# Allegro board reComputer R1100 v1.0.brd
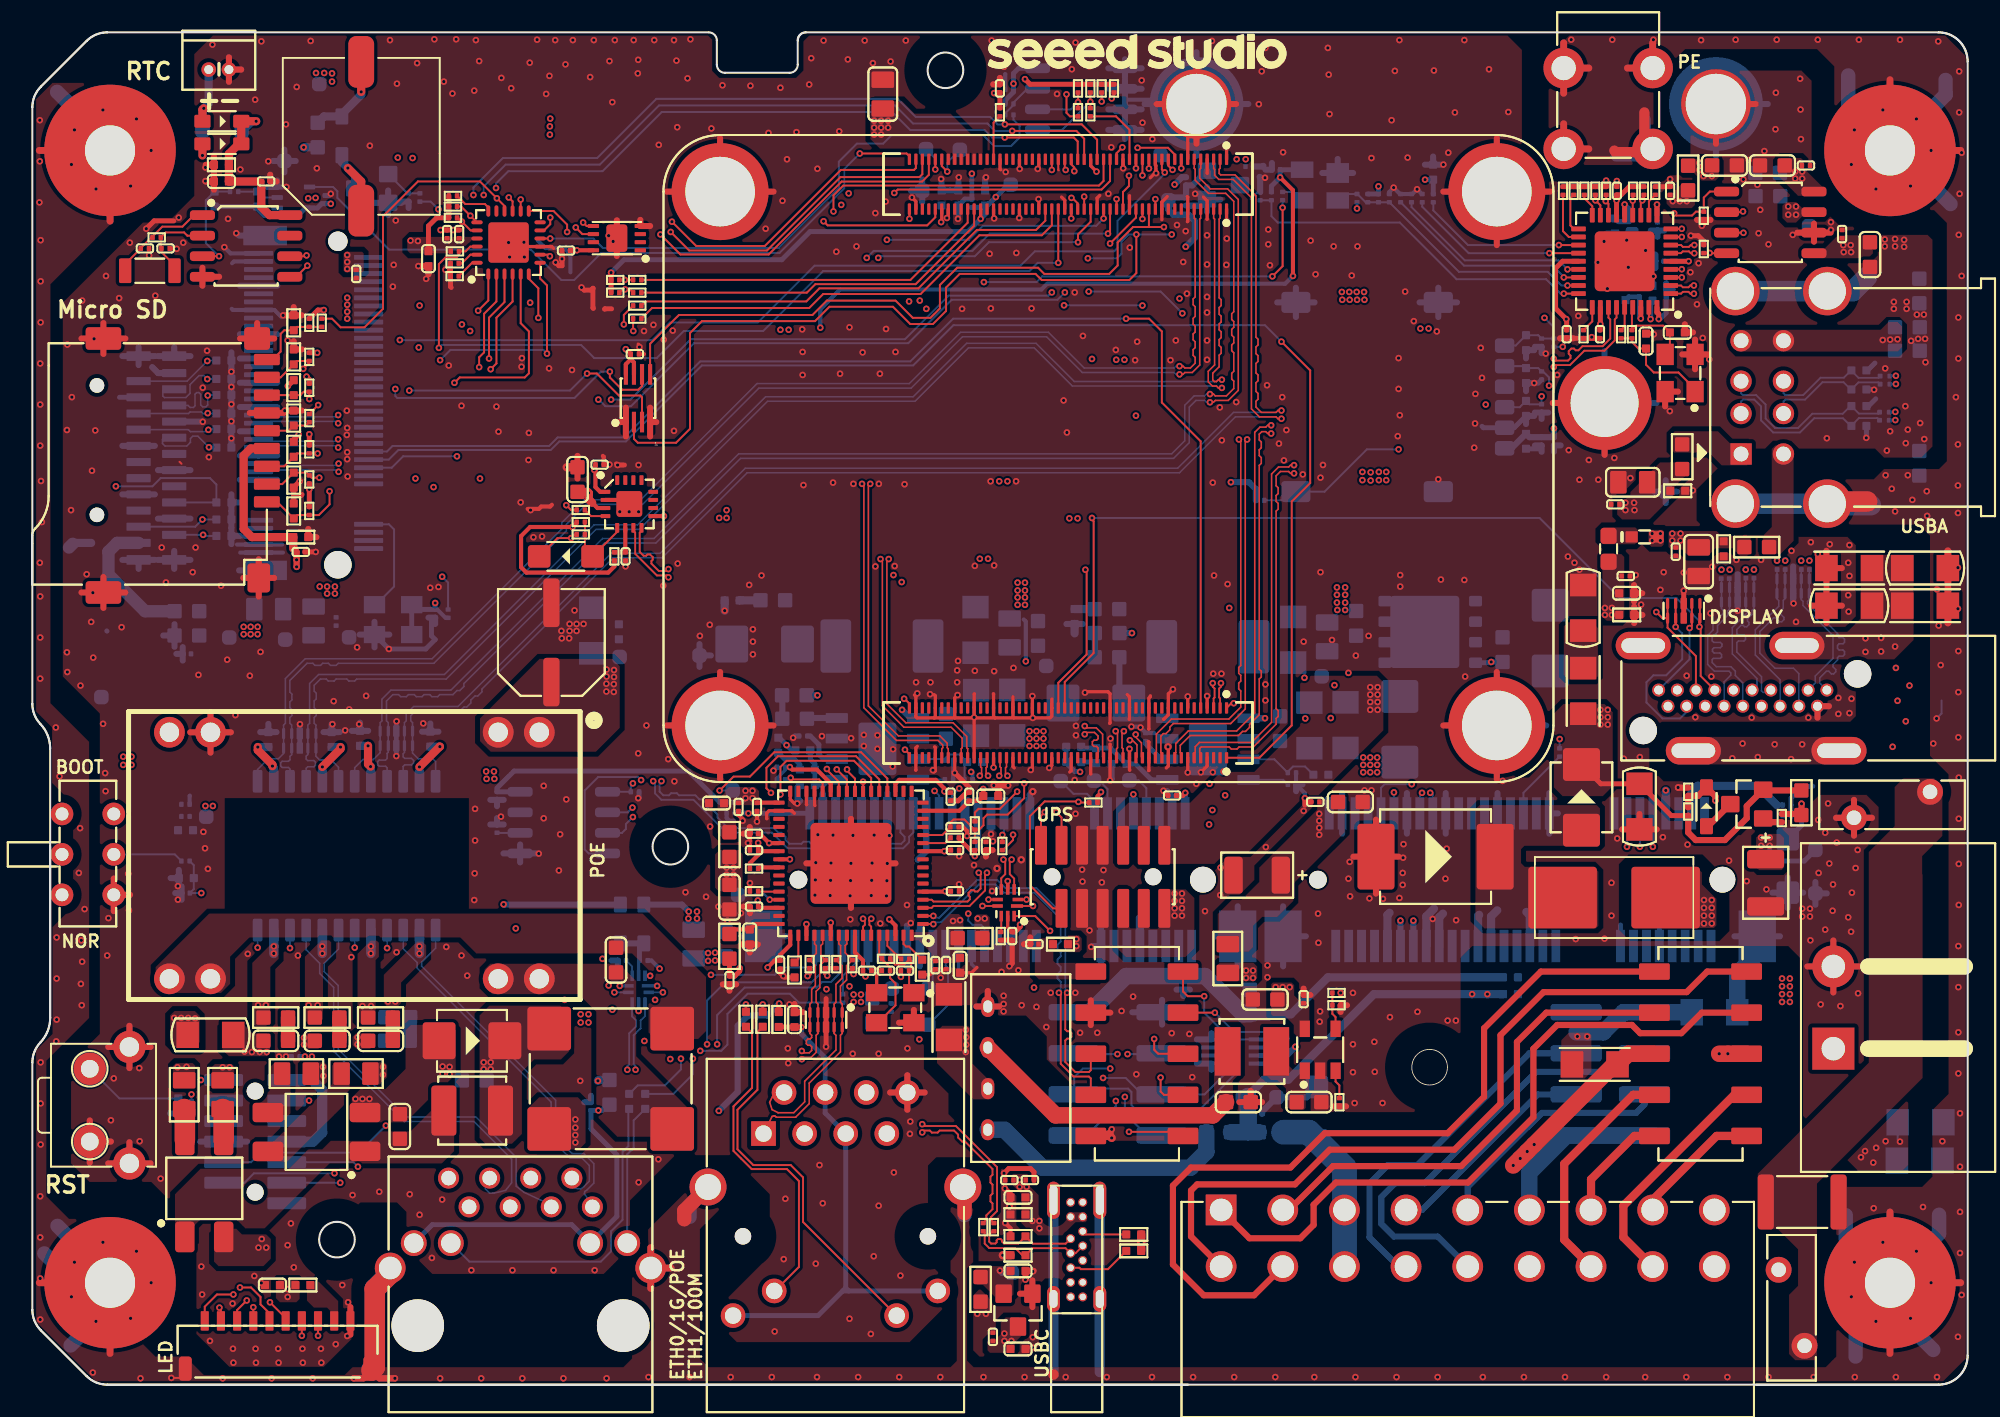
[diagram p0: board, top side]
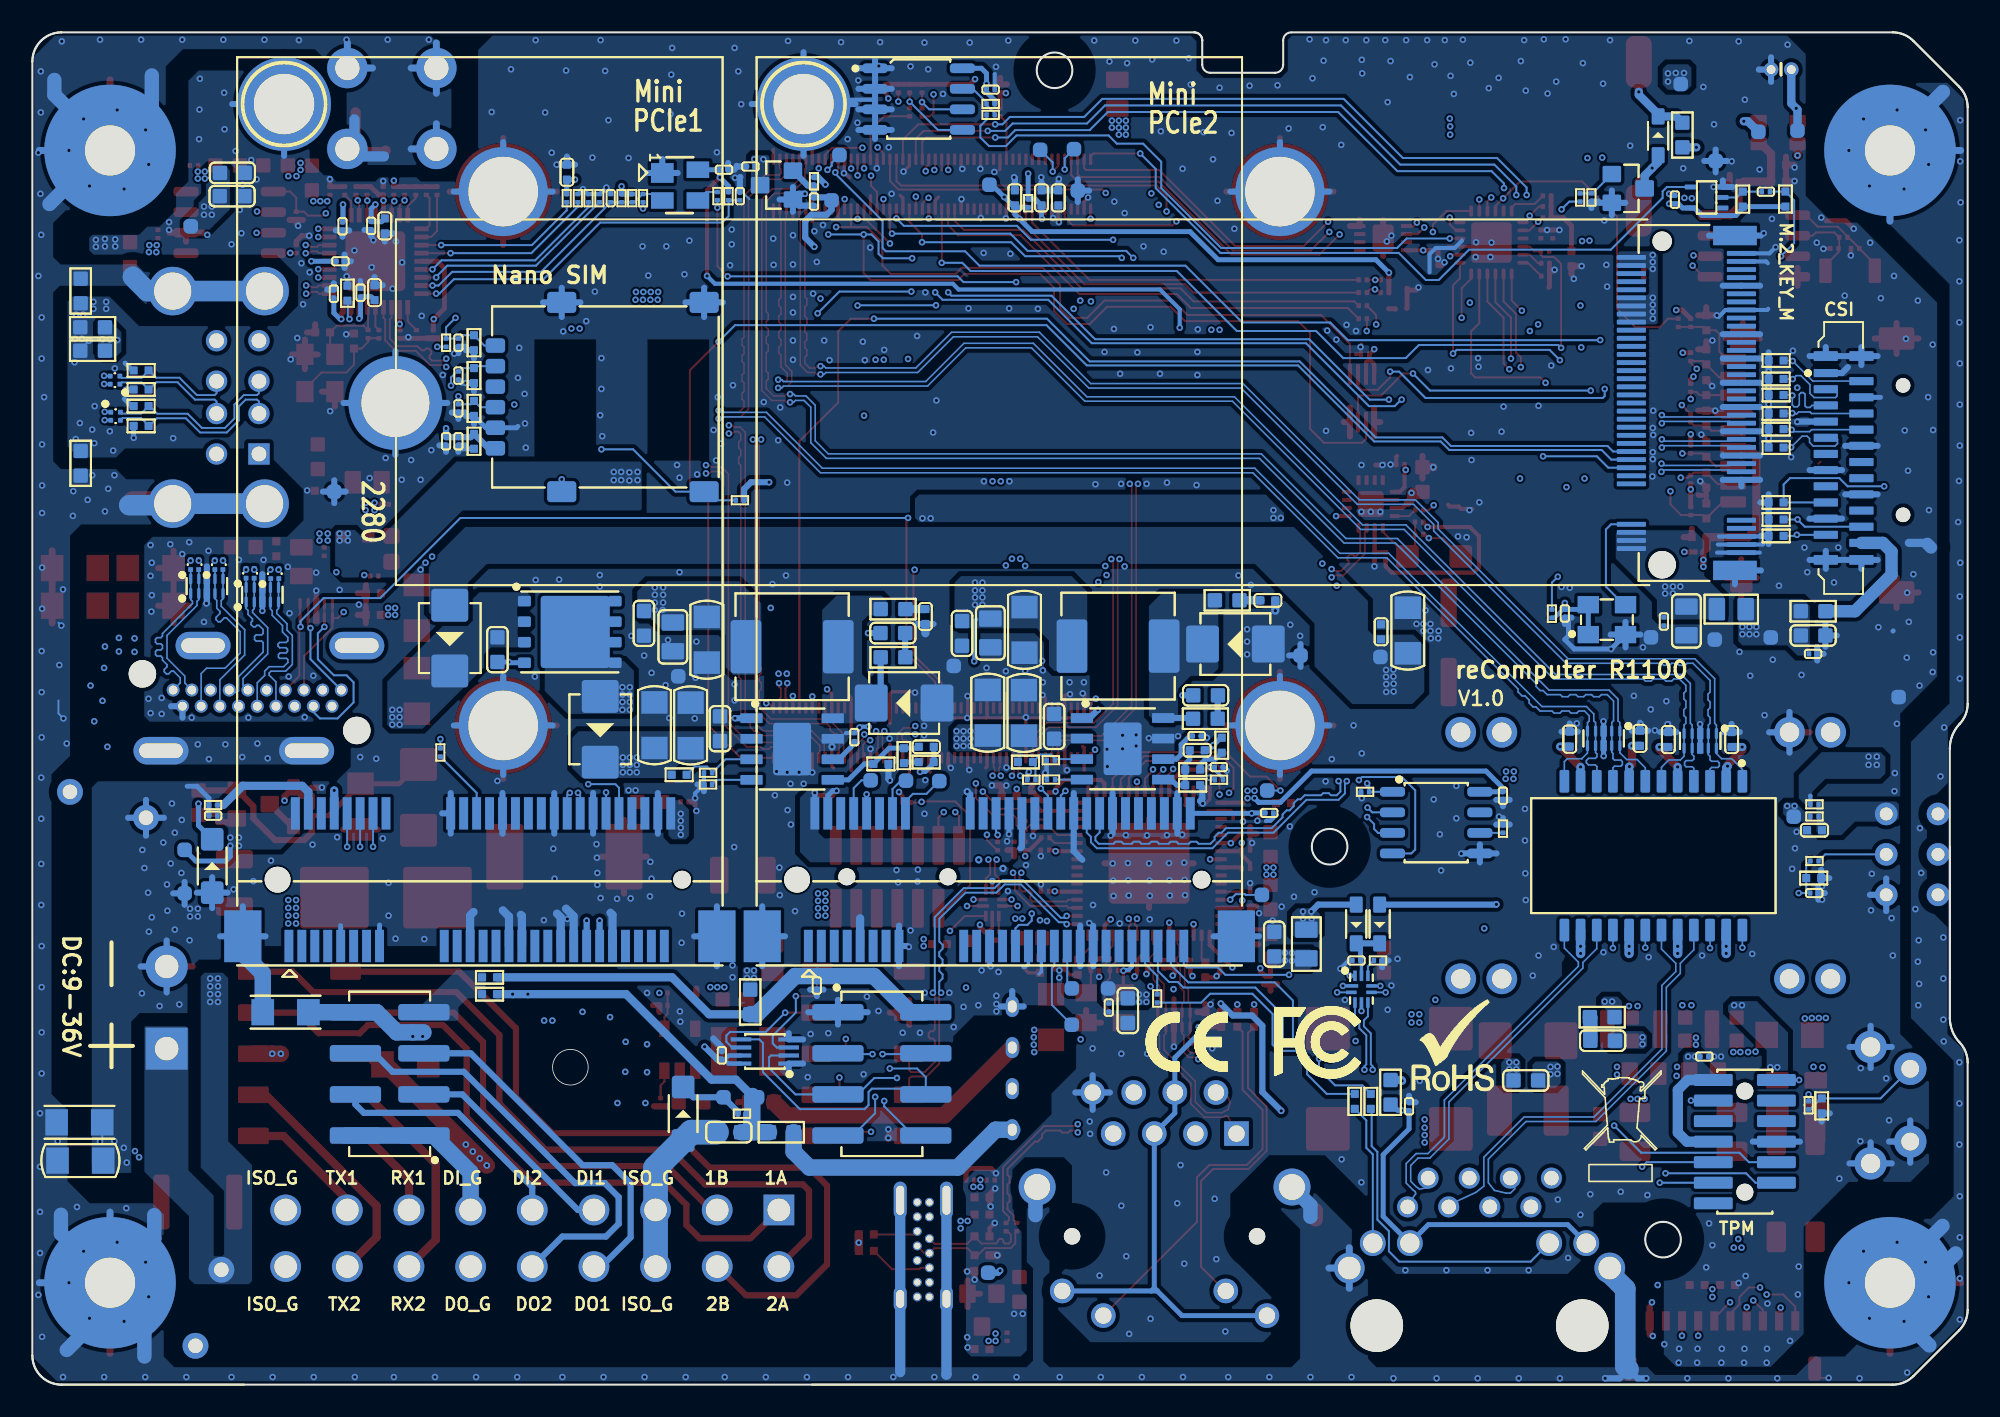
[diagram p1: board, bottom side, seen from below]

Outline 119.6 x 83.6 mm; copper layers: TOP, LYR2_GND, LYR3, LYR4_GND, LYR5_PWR, LYR6, LYR7_GND, BOTTOM. Coordinates in mm from the lower left corner of the outline.
Outline path: circle c18.82,8.97 r1.1 ; circle c18.82,8.97 r1.1 ; circle c39.43,33.26 r1.1 ; circle c39.43,33.26 r1.1 ; circle c56.43,81.25 r1.1 ; circle c56.43,81.25 r1.1 ; circle c86.35,19.62 r1.1 ; 0,78.97 0,42.09 ; 0,78.97 arc(0.14,79.66) 0.53,80.24 ; 0,78.97 arc(0.14,79.66) 0.53,80.24 ; 0,42.09 arc(0.13,41.42) 0.5,40.85 ; 0,42.09 arc(0.13,41.42) 0.5,40.85 ; 0.53,80.24 3.36,83.07 ; 0.53,80.24 3.36,83.07 ; 0,19.91 0,4.63 ; 0,19.91 arc(0.13,20.58) 0.5,21.15 ; 0,19.91 arc(0.13,20.58) 0.5,21.15 ; 0,4.63 arc(0.14,3.94) 0.53,3.36 ; 0,4.63 arc(0.14,3.94) 0.53,3.36 ; 0.5,21.15 arc(0.94,21.85) 1.1,22.67 ; 0.5,21.15 arc(0.94,21.85) 1.1,22.67 ; 0.5,40.85 arc(0.94,40.15) 1.1,39.33 ; 0.5,40.85 arc(0.94,40.15) 1.1,39.33 ; 1.1,39.33 1.1,22.67 ; 3.36,83.07 arc(3.94,83.46) 4.63,83.6 ; 3.36,83.07 arc(3.94,83.46) 4.63,83.6 ; 0.53,3.36 3.36,0.53 ; 0.53,3.36 3.36,0.53 ; 3.36,0.53 arc(3.94,0.14) 4.63,0 ; 3.36,0.53 arc(3.94,0.14) 4.63,0 ; 1.1,22.67 1.1,33.26 ; 4.63,83.6 41.8,83.6 arc(42.15,83.45) 42.3,83.1 42.3,81.6 arc(42.45,81.25) 42.8,81.1 46.8,81.1 arc(47.15,81.25) 47.3,81.6 47.3,83.1 ; 4.63,0 71.42,0 ; 4.63,0 117.8,0 ; 117.8,0 106.52,0 ; 117.8,0 arc(119.07,0.53) 119.6,1.8 ; 117.8,0 arc(119.07,0.53) 119.6,1.8 ; 47.3,83.1 arc(47.45,83.45) 47.8,83.6 ; 47.3,83.1 arc(47.45,83.45) 47.8,83.6 ; 47.8,83.6 117.8,83.6 ; 117.8,83.6 arc(119.07,83.07) 119.6,81.8 ; 117.8,83.6 arc(119.07,83.07) 119.6,81.8 ; 119.6,81.8 119.6,1.8

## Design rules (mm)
constraint set DEFAULT: min track width 0.121
net group CAM0_C: nets CAM0_C_N CAM0_C_P
net group CAM0_D0: nets CAM0_D0_N CAM0_D0_P
net group CAM0_D1: nets CAM0_D1_N CAM0_D1_P
net group DP_HDMI0_CLK_N1: nets HDMI0_CLK_N HDMI0_CLK_P
net group DP_HDMI0_TX0: nets HDMI0_TX0_N HDMI0_TX0_P
net group DP_HDMI0_TX1_N1: nets HDMI0_TX1_N HDMI0_TX1_P
net group DP_HDMI0_TX2_N1: nets HDMI0_TX2_N HDMI0_TX2_P
net group ETHERNET0: nets ETHERNET_PAIR0_N ETHERNET_PAIR0_P
net group ETHERNET1: nets ETHERNET_PAIR1_N ETHERNET_PAIR1_P
net group ETHERNET2: nets ETHERNET_PAIR2_N ETHERNET_PAIR2_P
net group ETHERNET3: nets ETHERNET_PAIR3_N ETHERNET_PAIR3_P
net group ETHERNET_RX_P: nets ETHERNET_RX_N ETHERNET_RX_P
net group ETHERNET_TX_P: nets ETHERNET_TX_N ETHERNET_TX_P
net group HDMI0_CLK_N1: nets HDMI0_CLK_N1 HDMI0_CLK_P1
net group HDMI0_TX0_N1: nets HDMI0_TX0_N1 HDMI0_TX0_P1
net group HDMI0_TX1_N1: nets HDMI0_TX1_N1 HDMI0_TX1_P1
net group HDMI0_TX2_N1: nets HDMI0_TX2_N1 HDMI0_TX2_P1
net group N21891930: nets N21891930 N21894342
net group N23452007: nets N23452007 N23452027
net group PCIE_CLK: nets PCIE_CLK_N PCIE_CLK_P
net group PCIE_RX: nets PCIE_RX_N PCIE_RX_P
net group PCIE_TX: nets PCIE_TX_N PCIE_TX_P
net group RJ_12: nets N22026897 N22026906
net group RJ_36: nets N22026915 N22078660
net group RJ_45: nets N22078676 N22078685
net group RJ_78: nets N22026957 N22026966
net group UART_3V3: nets UART_3V3 V3
net group USB_0: nets USB_0M USB_0P
net group USB_1P: nets USB_1M USB_1P
net group USB_D: nets USB_DM USB_DP
net group USB_HUB1_DM2: nets USB_HUB1_DM2 USB_HUB1_DP2
net group USB_HUB1_DM3: nets USB_HUB1_DM3 USB_HUB1_DP3
net group USB_HUB2_D1: nets USB_HUB2_DM1 USB_HUB2_DP1
net group USB_HUB2_D2: nets USB_HUB2_DM2 USB_HUB2_DP2
net group USB_HUB2_D3: nets USB_HUB2_DM3 USB_HUB2_DP3
net group USB_HUB2_D4: nets USB_HUB2_DM4 USB_HUB2_DP4
net group USB_HUB2_DP1_01: nets N23711005 N23711301
net group USB_HUB2_DP2_01: nets N23452966 N23452985
net group USB_TO_UART: nets USB_TO_UART_DM USB_TO_UART_DP
net group USBC: nets USB_C_DM USB_C_DP
net group USBC_DM: nets USBC_DM USBC_DP
net group VDD33_HUB1: nets N23370571 N23401903
net group +1.8V_OUT: nets USIM_1V8
net group +3.3V_OUT: nets +3.3V_OUT CM4_GPIO_VREF SD_VDD_OVERRIDE

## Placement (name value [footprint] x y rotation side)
B1  HPD-9603S-3  [BUZZER2P_8D4_9_6X9_6X5_5MM]  20.32 77.18 0 top
C1  100nF  [C0603]  90.86 45.44 270 bottom
C2  10uF  [C1206]  99.32 35.74 270 top
C3  4.7uF  [C1206]  95.84 48.03 90 top
C4  100nF  [C0201]  71.12 24.67 270 bottom
C5  100nF  [C0603]  66.42 46.46 180 bottom
C6  4.7uF  [C0402]  59.23 36.39 0 top
C7  10uF  [C1206]  78.92 40.76 90 bottom
C8  10uF  [C1206]  81.16 40.77 90 bottom
C9  100nF  [C0603]  77.11 40.55 90 bottom
C10  100nF  [C0603]  81.81 47.07 270 bottom
C11  22uF  [C0805]  80.02 46.23 270 bottom
C12  100uF  [C1206]  77.92 46.05 270 bottom
C13  100uF  [C1206]  58.29 46.66 270 bottom
C14  100nF  [C0201]  44.59 34.06 180 top
C15  10nF  [C0201]  68.8 40.03 90 bottom
C16  150pF  [C0402]  64.41 47.49 270 bottom
C17  150pF  [C0402]  64.35 39.43 0 bottom
C18  100nF  [C0603]  47.09 42.62 180 bottom
C19  100nF  [C0201]  57.9 36.35 90 top
C20  10uF  [C1206]  60.56 41.54 90 bottom
C21  10uF  [C1206]  58.32 41.53 90 bottom
C22  100nF  [C0603]  56.46 40.69 90 bottom
C23  100nF  [C0603]  62.15 46.44 270 bottom
C24  22uF  [C0805]  60.39 46.47 270 bottom
C28  10nF  [C0201]  47.64 40.1 180 bottom
C29  150pF  [C0402]  43.25 48.48 180 bottom
C30  150pF  [C0402]  47.61 39.22 0 bottom
C31  22uF  [C0805]  52.56 79.78 90 top
C32  100nF  [C0201]  59.79 80.13 90 top
C33  10uF  [C0402]  57.23 73.37 270 bottom
C34  10uF  [C0402]  56.2 73.37 270 bottom
C35  1uF  [C0402]  58.88 73.37 270 bottom
C36  1uF  [C0402]  9.47 34.28 0 bottom
C37  100nF  [C0201]  9.48 30.39 180 bottom
C38  100nF  [C0201]  60.56 27.73 270 top
C40  100nF  [C0201]  46.28 38.18 180 bottom
C41  100nF  [C0201]  44.78 35.71 270 top
C42  10uF  [C0603]  43.08 30.14 270 top
C43  100nF  [C0201]  43.64 35.71 270 top
C44  4.7uF  [C0402]  42.28 35.95 180 top
C45  100nF  [C0201]  44.6 29.56 180 top
C46  100nF  [C0201]  44.6 33.04 180 top
C47  100nF  [C0201]  56.75 36.35 270 top
C48  4.7uF  [C0402]  57.33 25.92 270 top
C49  100nF  [C0201]  55.8 25.94 270 top
C50  100nF  [C0201]  51.59 25.59 0 top
C51  100nF  [C0201]  57.02 33.04 0 top
C52  100nF  [C0201]  56.47 25.94 270 top
C53  100nF  [C0201]  46.21 25.97 270 top
C54  100nF  [C0201]  57.02 30.5 0 top
C55  100nF  [C0201]  56.99 34.48 0 top
C56  12pF  [C0201]  53.93 25.59 180 top
C57  12pF  [C0201]  52.75 25.59 180 top
C58  10uF  [C0603]  104.57 75.37 0 top
C59  100nF  [C0201]  101.21 73.81 90 top
C60  100nF  [C0201]  75.88 73.47 90 bottom
C61  100nF  [C0201]  83.86 73.35 90 bottom
C62  100nF  [C0201]  100.43 71.61 270 bottom
C63  100nF  [C0201]  96.88 64.94 270 top
C64  100nF  [C0201]  94.82 64.94 270 top
C65  100nF  [C0201]  100.56 69.45 180 bottom
C66  100nF  [C0201]  100.97 67.44 90 bottom
C67  100nF  [C0201]  97.92 73.81 90 top
C68  100nF  [C0201]  76.86 75.11 180 bottom
C69  1uF  [C0402]  98.45 67.51 270 bottom
C70  10nF  [C0201]  99.32 67.5 270 bottom
C71  1uF  [C0402]  97.82 71.64 90 bottom
C72  10nF  [C0201]  98.66 71.64 90 bottom
C73  1uF  [C0402]  86.57 74.96 90 bottom
C74  33pF  [C0402]  99.73 64.52 90 top
C75  33pF  [C0402]  101.66 65.05 0 top
C76  10uF  [C0805]  98.9 55.79 0 top
C77  10uF  [C0805]  102.98 50.88 270 top
C78  100nF  [C0201]  97.83 54.42 0 top
C79  100nF  [C0201]  101.56 51.5 270 top
C80  10uF  [C0603]  107.26 73.47 180 bottom
C81  10uF  [C0603]  107.24 74.91 180 bottom
C82  10uF  [C0603]  107.53 75.37 180 top
C83  100nF  [C0201]  109.61 75.37 0 top
C84  10uF  [C0603]  113.56 69.86 270 top
C85  100nF  [C0201]  111.84 71.13 90 top
C86  100nF  [C0201]  98.47 49.99 0 top
C87  1uF  [C0402]  98.52 48.92 0 top
C88  22nF  [C0402]  47.1 22.57 90 top
C89  1uF  [C0402]  24.48 69.61 270 top
C90  100nF  [C0201]  26.38 71.13 90 top
C91  100nF  [C0201]  25.63 71.13 90 top
C92  1uF  [C0402]  60.91 11.58 180 top
C93  100nF  [C0201]  61.65 12.65 0 top
C94  100nF  [C0201]  60.38 12.65 180 top
C95  1uF  [C0402]  60.91 2.21 0 top
C96  100nF  [C0201]  59.36 2.96 90 top
C97  1uF  [C0402]  60.91 7.03 0 top
C98  100nF  [C0201]  37.77 26.22 0 bottom
C99  10uF  [C0603]  33.69 55.95 270 top
C100  100nF  [C0201]  35.06 56.87 180 top
C101  100nF  [C0201]  36.66 51.2 90 top
C102  18pF  [C0201]  8.23 70.24 180 top
C103  18pF  [C0201]  6.95 70.24 0 top
C104  1uF  [C0402]  11.68 74.38 180 top
C105  100nF  [C0201]  14.44 74.39 0 top
C106  100nF  [C0201]  16.27 20.28 180 bottom
C107  100nF  [C0201]  60.38 80.06 180 bottom
C108  100nF  [C0201]  18.09 73.26 90 bottom
C109  100nF  [C0201]  12.47 73.75 0 bottom
C110  100nF  [C0201]  32.98 70.11 0 top
C111  100nF  [C0201]  108.43 35.17 0 bottom
C112  100nF  [C0201]  70.44 36.42 0 top
C113  100nF  [C0201]  53.08 23.31 90 bottom
C114  100nF  [C0201]  43.16 35.34 0 bottom
C115  100nF  [C0201]  75.22 75.31 180 bottom
C116  100nF  [C0201]  71.3 73.14 90 bottom
C117  10uF  [C0603]  42.85 27.23 90 bottom
C118  10uF  [C0603]  51.9 23.13 270 bottom
C119  100nF  [C0201]  58.93 33.3 270 top
C120  100nF  [C0201]  93.27 58.32 270 bottom
C121  33pF  [C0201]  94.03 58.32 270 bottom
C122  33pF  [C0201]  93.27 64.41 270 bottom
C123  33pF  [C0201]  93.27 62.38 270 bottom
C124  10uF  [C0603]  81.45 36.02 0 top
C125  100nF  [C0201]  79.29 36.03 180 top
C126  47uF  [AVX_B]  75.69 31.5 180 top
C127  47uF  [AVX_B]  107.11 31.03 270 top
C128  33pF  [C0201]  93.27 60.35 270 bottom
C129  100nF  [C0201]  16.59 51.48 180 top
C130  10uF  [C0603]  76.18 23.81 180 top
C131  100nF  [C0201]  78.56 23.84 90 top
C132  10uF  [C0603]  78.89 17.47 0 top
C133  10uF  [C0603]  74.53 17.47 0 top
C134  10uF  [C0603]  76.56 15.61 0 bottom
C135  1nF  [C1206]  116.97 50.48 0 top
C136  1nF  [C1206]  112.28 48.16 0 top
C144  100uF  [ELECTRO_SMD_6_6X6_6MM]  32.08 45.88 0 top
C145  10uF  [C1206]  34.6 46.62 90 bottom
C146  100nF  [C0402]  36.25 46.54 90 bottom
C147  10nF  [C0603]  36.07 26.25 90 top
C148  10nF  [C0603]  27.31 18.81 180 bottom
C149  10nF  [C0603]  22.71 15.96 90 top
C150  100nF  [C0402]  14.58 39.88 90 bottom
C151  100nF  [C0402]  18.5 39.88 90 bottom
C152  100nF  [C0402]  20.25 39.96 90 bottom
C153  100nF  [C0402]  24.59 39.91 90 bottom
C154  22nF  [C0603]  15.04 21.26 180 top
C155  22nF  [C0603]  18.21 21.26 180 top
C156  22nF  [C0603]  21.52 21.26 180 top
C157  22nF  [C0603]  22.56 21.26 180 bottom
C158  1nF  [C1206]  11.01 21.62 180 top
C159  1nF  [C1206]  116.63 13.85 0 bottom
C160  100nF  [C0201]  34.52 17.21 90 bottom
C163  4.7uF  [C0402]  14.84 6.16 180 top
C166  22uF  [C0805]  17.38 47.21 270 bottom
C167  100nF  [C0201]  18.77 47.18 270 bottom
C168  100nF  [C0201]  24.89 47.67 270 bottom
C169  100nF  [C0201]  20.02 68.67 270 top
C204  100nF  [C0201]  61.93 27.23 180 top
C500  100nF  [C0201]  28.72 36.41 270 bottom
C501  100nF  [C0201]  43.08 25 270 top
C502  1uF  [C0402]  44.33 27.68 270 top
C503  10uF  [C0603]  9.55 46.31 180 bottom
C504  100nF  [C0201]  9.55 45.18 180 bottom
C508  100nF  [C0201]  37.24 63.71 0 top
C509  100nF  [C0201]  76.99 20.36 90 bottom
D1  SM360B  [DO_214AA_SMB]  93.8 46.15 270 bottom
D2  SM360B  [DO_214AA_SMB]  84.51 40.51 270 bottom
D3  SM360B  [DO_214AA_SMB]  95.74 36.31 90 top
D5  SMCJ40CA  [DO_214AB_SMC]  86.72 32.64 0 top
D8  MMSZ5259A  [SOD_123]  108.49 32.07 90 bottom
D9  B5819WS SL  [SOD_323]  103.46 35.72 90 top
D10  SM360B  [DO_214AA_SMB]  65.73 42.14 0 bottom
D11  SM360B  [DO_214AA_SMB]  45.25 45.78 0 bottom
D12  ESDPSA0402V05  [D0402]  9.02 17.23 90 bottom
D13  B5819WS SL  [SOD_323]  19.13 77.2 90 bottom
D14  ESDPSA0402V05  [D0402]  112.88 60.5 180 bottom
D15  ESDPSA0402V05  [D0402]  112.88 59.27 180 bottom
D16  ESDPSA0402V05  [D0402]  101.68 55.26 180 top
D17  ESDPSA0402V05  [D0402]  104.52 51.67 90 top
D18  ESDPSA0402V05  [D0402]  112.88 61.52 180 bottom
D19  ESDPSA0402V05  [D0402]  112.88 62.7 180 bottom
D20  ESDPSA0402V05  [D0402]  98.53 47.59 180 top
D21  ESDPSA0402V05  [D0402]  60.91 10.52 0 top
D22  ESDPSA0402V05  [D0402]  60.91 8 0 top
D23  ESDPSA0402V05  [D0402]  60.91 9.17 0 top
D24  B5819WS SL  [SOD_323]  36.34 28.48 270 bottom
D25  B5819WS SL  [SOD_323]  37.79 28.48 270 bottom
D26  B0540W  [SOD_123]  32.97 51.2 180 top
D27  B5819WS SL  [SOD_323]  11.71 76.71 0 top
D28  ESDPSA0402V05  [D0402]  11.69 75.41 0 top
D29  B5819WS SL  [SOD_323]  11.71 78.1 0 top
D30  TPD1E1B04DPY  [D0402]  92.31 64.41 90 bottom
D31  TPD1E1B04DPY  [D0402]  92.31 62.38 90 bottom
D32  TPD1E1B04DPY  [D0402]  92.31 60.35 90 bottom
D33  TPD1E1B04DPY  [D0402]  92.31 58.32 90 bottom
D34  MMSZ5232BT1G  [SOD_123]  79.38 16.75 90 bottom
D37  TPD1E1B04DPY  [D0402]  16.15 54.01 270 top
D38  TPD1E1B04DPY  [D0402]  16.15 55.92 90 top
D39  TPD1E1B04DPY  [D0402]  16.15 57.82 270 top
D40  TPD1E1B04DPY  [D0402]  16.59 52.39 180 top
D41  TPD1E1B04DPY  [D0402]  16.15 59.75 270 top
D42  TPD1E1B04DPY  [D0402]  16.15 61.63 270 top
D43  TPD1E1B04DPY  [D0402]  16.15 63.54 270 top
D44  TPD1E1B04DPY  [D0402]  16.15 65.65 270 top
D50  SMBJ58CA  [DO_214AA_SMB]  27.17 21.26 0 top
D51  U*  [SMD4P_4D7X3D8MM]  10.62 12.13 180 top
D52  U*  [SMD4P_4D7X3D8MM]  17.56 15.62 270 top
D53  ESDPSA0402V05  [D0402]  11.84 63.31 180 bottom
D54  ESDPSA0402V05  [D0402]  11.84 52.47 180 bottom
D55  ESDPSA0402V05  [D0402]  11.84 62.17 180 bottom
D56  ESDPSA0402V05  [D0402]  11.84 61.18 180 bottom
D57  ESDPSA0402V05  [D0402]  11.84 60.04 180 bottom
D58  ESDPSA0402V05  [D0402]  11.84 59.07 180 bottom
D59  ESDPSA0402V05  [D0402]  11.84 57.93 180 bottom
D60  ESDPSA0402V05  [D0402]  11.84 53.49 180 bottom
D63  LRB520S-30T1G  [SOD_523]  99.64 52.41 180 top
D64  ESDPSA0402V05  [D0402]  11.84 54.54 180 bottom
F1  5A  [FUSE2P_HOLDER_9_73X5_03X3_81MM]  97.75 30.11 180 top
F2  100mA  [F0603]  97.41 51.67 90 top
FB1  120R  [L0603]  43.08 33.39 90 top
FB2  120R  [L0603]  57.95 27.6 180 top
FB3  120R  [L0603]  43.08 27.1 270 top
FB4  120R  [L0603]  102.33 74.6 270 top
FB5  120R  [L0603]  101.96 57.37 90 top
FB6  120R  [L0603]  106.56 51.78 180 top
FB9  120R  [L0603]  35.66 18.07 270 bottom
FB15  120R  [L0603]  75.24 23.66 270 bottom
FB26  120R  [L0603]  9.55 47.81 0 bottom
FB27  120R  [L0402]  16.72 6.16 180 top
G1  4532-201-LF  [GDT2P_4D0_4_5X3_2X2_7MM]  109.37 11.29 180 top
J1  STP2EDGRM-X-5.08-2P  [TERMINAL_2P_5D08]  111.3 23.31 90 top
J2  Header 2x7Pin 1.27MM  [HEADER2X7P_1D27_SMD_NP_EPT14]  66.14 31.4 180 top
J3  PCB-69-M3  [SOLDERING_TERMINAL_4P_9X6_3X5MM]  97.38 78.89 270 top
J4  DF40C-100DS-0.4V(51)  [DF40_100P_0D4_22_6X3_38X1_5MM]  64 74.21 90 top
J5  DF40C-100DS-0.4V(51)  [DF40_100P_0D4_22_6X3_38X1_5MM_101_200]  64 40.29 90 top
J6  Toggle Switch_2CH  [SW6P_2D5_9X3_5X3_5MM]  3.43 32.78 270 top
J8  USB-AF-90  [ST-USB-201C]  110.93 61.03 270 top
J9  TYPE_A  [HDMI19P_1D155_23_1X7_7X16_4MM]  112.8 42.44 90 top
J10  LPJ0011BBNL  [RJ45-7499010211A]  45.19 15.52 0 top
J11  UBF31-112-14C1-024  [USB2_0_TYPE_C_14X3D16X8D94MM]  64.54 8.35 270 top
J12  Header 1x2 1.25mm  [HEADER2P_1D25_DIP]  11.52 81.3 0 top
J13  Header 2x7Pin 1.27MM  [HEADER2X7P_1D27_SMD_NP_EPT14]  13.77 15.02 270 bottom
J14  ST-PC-009  [PCIE52_0D8_56X30_2X4MM]  59.84 31.22 90 bottom
J15  ST-PC-009  [PCIE52_0D8_56X30_2X4MM]  91.95 31.22 90 bottom
J16  ST-SIM-N032  [SIM6_4P_1D27_14X12X1_4MM]  90.99 61.06 90 bottom
J17  ST-FH-254-0109-2X4P  [HEADER2X4P_2D54_SMD]  67.1 19.21 180 bottom
J18  DGKYD56A1188AB1A2DY1054  [RJ45_12_2P_2D54_16_3X15_8X12_85MM]  30.17 3.65 0 top
J20  ST-FH-254-0109-2X4P  [HEADER2X4P_2D54_SMD#2]  97.52 19.21 0 bottom
J21  WJ15EDGRHB-3.81-2x09P  [TERMINAL_2X9P_3D81_35_38X13_3X15_2MM]  88.71 10.8 0 top
J22  ST-FH-254-0166-2X5P  [HEADER2X5P_2D54_SMD_FEMALE]  68.26 20.46 90 top
J23  ST-FH-254-0166-2X5P  [HEADER2X5P_2D54_SMD_FEMALE]  103.09 20.46 90 top
J24  MTFP65-822SWN-19A72  [FPC22_0D5_16_7X3_5X3_95MM_90D]  7.67 57.29 90 bottom
J25  1.0-10A-LT  [JST10_2P_1D0_12_35X3_2X4_5MM]  15.15 3.94 0 top
J26  ST-TF-003J  [MICRO_SD_ST_TF_003A_16_1X14_5MM]  14.49 56.82 180 top
J62  MTSSD03-67MSW33  [CON_MINIPEX_067_SMT_RA_M2_KEY_M]  18.88 60.69 270 bottom
L2  10uH  [L6_6X7X1_6MM]  72.65 45.62 0 bottom
L3  10uH  [L6_6X7X1_6MM]  52.5 45.66 0 bottom
L4  90R  [L4P_0_85X0_65MM]  114.46 59.87 270 bottom
L5  90R  [L4P_0_85X0_65MM]  114.49 62.1 90 bottom
L11  6.8uH  [L4X4MM]  75.37 20.6 180 top
L15  3.3uH  [L4242]  27.18 16.94 180 top
L16  3200R  [L4P_10X8_7X6_5MM]  35.74 18.91 270 top
L19  90R  [L4P_0_85X0_65MM]  109.57 50.69 180 bottom
L20  90R  [L4P_0_85X0_65MM]  108.07 50.69 180 bottom
L21  90R  [L4P_0_85X0_65MM]  106.14 50.16 180 bottom
L22  90R  [L4P_0_85X0_65MM]  104.62 50.13 180 bottom
MH1  U*  [PTH_4_3MM_6D0]  42.5 73.75 0 top
MH2  U*  [PTH_4_3MM_6D0]  42.5 40.75 0 top
MH3  U*  [PTH_4_3MM_6D0]  90.5 40.75 0 top
MH4  U*  [PTH_4_3MM_6D0]  90.5 73.75 0 top
MH6  SMTSO2066CTJ  [PTH_3_73MM_5D8_PASTE]  71.94 79.17 180 bottom
MH7  SMTSO3003CTJ  [PTH_4_2MM_5D8]  97.16 60.69 180 bottom
MH10  SMTSO2066CTJ  [PTH_3_73MM_5D8_PASTE]  104.04 79.17 180 bottom
MH11  Hole 3.1MM  [PTH_3_1MM_8]  4.8 76.3 0 top
MH12  Hole 3.1MM  [PTH_3_1MM_8]  4.8 6.3 0 top
MH13  Hole 3.1MM  [PTH_3_1MM_8]  114.8 6.3 0 top
MH14  Hole 3.1MM  [PTH_3_1MM_8]  114.8 76.3 0 top
NOREF  -  []  -307.46 -238.04 0 top
NOREF#2  -  []  4.63 0 90 top
NOREF#3  -  []  0 78.97 0 top
OSC1  32.768KHz  [X4-SMD-3_2X2_5X1_0MM]  22.29 47.29 180 bottom
Q1  CJAC70P06  [SON8P_1D27_5X6X1MM]  86.39 46.53 180 bottom
Q2  MMBT3906LT  [SOT23]  105.95 35.89 90 top
Q3  2N7002,215  [SOT23]  20.97 73.95 270 bottom
R1  22R  [R0201]  65.38 78.66 90 top
R2  2.2K  [R0603]  109.32 35.97 270 top
R3  100K  [R0201]  102.33 35.43 90 top
R4  10R  [R1206]  95.84 42.89 90 top
R5  10K  [R0201]  108.12 35.03 270 top
R6  22R  [R0201]  64.62 78.66 270 top
R7  200K  [R0201]  102.33 36.65 90 top
R8  51K  [R0402]  79.63 37.7 180 bottom
R9  5.1R  [R0603]  66.41 44.97 0 bottom
R10  100K  [R0201]  77.84 37.83 180 bottom
R11  5.1R  [R0603]  66.41 47.94 180 bottom
R12  49.9K  [R0201]  77.85 37.1 0 bottom
R13  68K  [R0402]  65.74 38.89 90 bottom
R14  12K  [R0402]  67.16 38.37 180 bottom
R15  5.1R  [R0603]  47.11 41.17 0 bottom
R16  51K  [R0402]  58.23 38.49 180 bottom
R17  100K  [R0201]  56.66 38.6 180 bottom
R18  5.1R  [R0603]  45.76 48.49 180 bottom
R19  49.9K  [R0201]  56.65 37.41 0 bottom
R20  68K  [R0402]  47.89 38.02 0 bottom
R21  20K  [R0402]  47.89 37.06 180 bottom
R24  22R  [R0201]  37.38 65.9 0 top
R25  22R  [R0201]  37.38 66.7 0 top
R26  0R  [R0201]  59.79 78.66 90 top
R27  22R  [R0201]  37.38 67.51 0 top
R28  22R  [R0201]  37.38 68.3 0 top
R29  0R  [R0201]  58.06 73.04 90 bottom
R30  4.7K  [R0201]  36.02 67.51 0 top
R31  4.7K  [R0201]  36.02 68.3 0 top
R32  0R  [R0201]  9.47 35.13 0 bottom
R33  0R  [R0201]  9.47 35.88 0 bottom
R34  10K  [R0201]  9.47 32.37 0 bottom
R35  18K  [R0402]  9.51 31.32 180 bottom
R36  0R  [R0201]  9.83 17.27 90 bottom
R37  0R  [R0201]  59.84 27.73 270 top
R38  33R  [R0603]  17.63 77.25 90 bottom
R39  1K  [R0201]  23.95 73.39 90 bottom
R40  100K  [R0201]  23.25 73.39 270 bottom
R41  10K  [R0201]  57 33.81 180 top
R42  12K  [R0402]  54.99 25.81 90 top
R43  10K  [R0201]  44.6 31.9 0 top
R44  10K  [R0201]  58.24 33.3 90 top
R45  12.4K  [R0402]  47.11 25.63 90 top
R46  0R  [R0201]  58.24 34.57 270 top
R47  0R  [R0201]  53.94 26.32 180 top
R48  0R  [R0201]  44.6 30.51 180 top
R49  1M  [R0201]  52.76 26.33 180 top
R50  10K  [R0201]  46.27 37.4 180 bottom
R51  10K  [R0201]  76.57 73.47 270 bottom
R52  10K  [R0201]  83.19 73.35 270 bottom
R53  10K  [R0201]  95.86 64.94 90 top
R54  10K  [R0201]  85.89 73.35 270 bottom
R55  10K  [R0201]  85.23 73.35 270 bottom
R56  10K  [R0201]  84.56 73.35 270 bottom
R57  0R  [R0201]  100.3 73.81 90 top
R58  12K  [R0402]  100.13 67.47 90 bottom
R59  10K  [R0201]  82.53 73.35 270 bottom
R60  10K  [R0201]  98.92 73.81 90 top
R61  10K  [R0201]  96.59 73.81 90 top
R62  10K  [R0201]  95.25 73.81 90 top
R63  10K  [R0201]  86.58 73.35 90 bottom
R64  0R  [R0201]  77.27 73.48 90 bottom
R65  10K  [R0201]  99.6 73.81 90 top
R66  10K  [R0201]  97.26 73.81 90 top
R67  10K  [R0201]  95.91 73.81 90 top
R68  10K  [R0201]  94.59 73.81 90 top
R69  0R  [R0201]  98.18 64.94 90 top
R70  1M  [R0201]  98.85 64.94 90 top
R71  0R  [R0201]  81.86 73.35 90 bottom
R72  0R  [R0603]  115.88 65.37 0 bottom
R73  0R  [R0603]  115.88 63.92 0 bottom
R74  10K  [R0201]  103.29 70.21 270 top
R75  10K  [R0201]  103.29 72.26 90 top
R78  49.9R  [R0201]  50.68 26 90 top
R79  49.9R  [R0201]  49.68 26 90 top
R80  49.9R  [R0201]  49 26 90 top
R81  49.9R  [R0201]  48.04 26 90 top
R82  10R  [R0402]  46.13 22.58 270 top
R83  470R  [R0402]  44.1 22.59 270 top
R84  470R  [R0402]  45.14 22.59 270 top
R85  100K  [R0201]  25.99 73.49 0 top
R86  47K  [R0201]  17.11 65.65 270 top
R87  0R  [R0201]  17.88 65.65 270 top
R88  2.2K  [R0201]  25.99 72.83 0 top
R89  2.2K  [R0201]  25.99 72.14 0 top
R90  4.7K  [R0201]  26.11 70.06 0 top
R91  0R  [R0201]  35.97 51.2 90 top
R92  0R  [R0201]  26.1 69.32 180 top
R93  0R  [R0201]  26.1 68.53 180 top
R94  5.1K  [R0402]  68.06 8.27 0 top
R95  5.1K  [R0402]  68.06 9.29 0 top
R96  1K  [R0603]  58.6 5.89 270 top
R97  0R  [R0201]  36.44 26.22 180 bottom
R98  4.7K  [R0201]  33.89 53.33 0 top
R99  0R  [R0201]  33.89 52.56 180 top
R100  33R  [R0201]  33.89 54.07 180 top
R101  1M  [R0201]  7.68 70.93 180 top
R102  10K  [R0201]  60.38 79.17 0 bottom
R103  0R  [R0201]  60.38 78.5 0 bottom
R104  510K  [R0402]  11.26 73.29 90 bottom
R105  510K  [R0402]  13.9 73.29 90 bottom
R106  2.2K  [R0201]  64.62 80.13 270 top
R107  2.2K  [R0201]  65.38 80.13 270 top
R108  0R  [R0201]  108.43 35.83 0 bottom
R109  0R  [R0201]  94.39 39.08 90 bottom
R110  0R  [R0201]  59.95 33.3 270 top
R111  0R  [R0201]  50.08 23.87 90 bottom
R112  0R  [R0201]  71.3 74.39 90 bottom
R113  0R  [R0805]  40.87 27.24 270 bottom
R114  10K  [R0201]  75.87 54.67 0 bottom
R115  15K  [R0201]  94.03 64.41 90 bottom
R116  0R  [R0805]  73.88 26.34 90 top
R117  0R  [R0603]  73.32 15.61 0 bottom
R118  0R  [R0201]  75.75 16.75 0 bottom
R119  100K  [R0201]  80.6 23.46 0 top
R120  15K  [R0201]  80.77 17.46 270 top
R122  0R  [R0201]  80.6 24.22 180 top
R123  1M  [R1206]  56.64 22.72 270 top
R124  47K  [R0201]  17.11 54.01 270 top
R125  47K  [R0201]  17.11 55.96 90 top
R126  10K  [R0201]  17.11 57.82 270 top
R127  47K  [R0201]  17.11 61.63 270 top
R128  47K  [R0201]  17.11 63.54 270 top
R129  0R  [R0201]  17.11 59.75 270 top
R130  0R  [R1206]  112.28 50.48 0 top
R131  0R  [R1206]  116.97 48.16 0 top
R151  0R  [R0805]  9.39 17.93 90 top
R152  0R  [R0805]  11.76 17.93 90 top
R153  0R  [R0805]  20 19.23 0 top
R154  0R  [R0805]  16.32 19.23 0 top
R155  470R  [R0402]  36.88 17.51 270 bottom
R156  75R  [R0603]  15.04 22.69 0 top
R157  75R  [R0603]  18.21 22.69 0 top
R158  75R  [R0603]  21.52 22.69 0 top
R159  75R  [R0603]  22.58 22.72 0 bottom
R160  470R  [R0402]  37.87 17.51 270 bottom
R161  0R  [R1206]  116.69 16.22 0 bottom
R163  0R  [R0402]  91.35 24.14 0 bottom
R164  0R  [R0402]  91.35 25.18 0 bottom
R165  0R  [R1206]  96.55 19.8 180 top
R166  0R  [R1206]  103.95 23.02 180 bottom
R175  10K  [R0201]  25.69 47.66 90 bottom
R176  0R  [R0805]  14.61 47.94 0 bottom
R177  4.7K  [R0201]  66.84 80.13 270 top
R178  4.7K  [R0201]  66.08 80.13 270 top
R181  0R  [R0201]  57.86 37.4 180 bottom
R182  820KD07  [CAP_5D0_9X3X12MM]  108.72 4.75 270 top
R183  820KD07  [CAP_5D0_9X3X12MM]  114.93 35.85 180 top
R530  22R  [R0201]  59.42 9.74 90 top
R531  22R  [R0201]  58.76 9.74 90 top
R532  0R  [R0402]  63.54 27.23 180 top
R573  10K  [R0201]  37.24 36.65 0 bottom
R632  0R  [R0603]  116.61 56.96 90 bottom
R633  0R  [R0603]  116.61 67.61 270 bottom
R651  0R  [R0201]  28.72 34.37 270 bottom
R652  49.9R  [R0402]  64.36 38.49 0 bottom
R653  49.9R  [R0402]  46.1 39.53 270 bottom
R654  100K  [R0201]  65.57 35.99 180 top
SW1  TC-1105AH-5.0H-250  [BUTTON4P_7_2X7_5X7MM]  6 17.28 90 top
T1  LP82441ANL  [TRF24P_1D0_15_1X7_1X4MM]  19.42 32.7 0 bottom
TP1  Test Point  [TP35S_SMD]  17.73 80.4 90 bottom
TP2  Test Point  [TP35S_SMD]  19.57 46.2 90 bottom
TP3  Test Point  [TP35S_SMD]  4.26 42.51 90 bottom
TP4  Test Point  [TP35S_SMD]  79.68 43.79 180 bottom
TP5  Test Point  [TP35S_SMD]  62.66 44.43 90 bottom
TP6  Test Point  [TP35S_SMD]  41.23 45.08 0 bottom
TP7  Test Point  [TP35S_SMD]  110.19 30.37 0 bottom
TP8  Test Point  [TP35S_SMD]  15.63 46.06 0 bottom
TP9  Test Point  [TP35S_SMD]  100.94 55.21 0 bottom
TP10  Test Point  [TP35S_SMD]  109.81 71.61 270 bottom
TP11  Test Point  [TP35S_SMD]  12.17 46.19 270 bottom
TP12  Test Point  [TP35S_SMD]  69.72 76.01 0 bottom
TP13  Test Point  [TP35S_SMD]  15.57 75.65 270 bottom
TP14  Test Point  [TP35S_SMD]  57.32 76.34 270 bottom
TP15  Test Point  [TP35S_SMD]  55.23 76.38 270 bottom
TP16  Test Point  [TP35S_SMD]  60.45 74.18 180 bottom
TP17  Test Point  [TP35S_SMD]  54.99 73.81 180 bottom
TP18  Test Point  [TP35S_SMD]  43.28 36.73 180 bottom
TP19  Test Point  [TP35S_SMD]  43.61 30.28 180 bottom
TP20  Test Point  [TP35S_SMD]  10.75 35.11 180 bottom
TP21  Test Point  [TP35S_SMD]  60.53 6.92 270 bottom
TP22  Test Point  [TP35S_SMD]  12.93 77.45 0 bottom
TP23  Test Point  [TP35S_SMD]  10.52 77.53 270 bottom
TP24  Test Point  [TP35S_SMD]  67.8 37.36 270 bottom
TP25  Test Point  [TP35S_SMD]  65.61 37.34 180 bottom
TP26  Test Point  [TP35S_SMD]  63.55 37.31 180 bottom
TP27  Test Point  [TP35S_SMD]  55.36 22.25 270 bottom
TP28  Test Point  [TP35S_SMD]  55.36 24.5 0 bottom
TP29  Test Point  [TP35S_SMD]  70.21 73.21 180 bottom
TP30  Test Point  [TP35S_SMD]  53.12 24.49 270 bottom
TP31  Test Point  [TP35S_SMD]  110.19 33.06 90 bottom
TP32  Test Point  [TP35S_SMD]  74.81 17.77 270 bottom
TP33  Test Point  [TP35S_SMD]  76.89 17.77 90 bottom
TP34  Test Point  [TP35S_SMD]  36.29 44.99 180 bottom
U1  SGM61630A  [SOP8_1D27_5X4X1_7MM]  72.65 39.29 180 bottom
U2  SGM61630A  [SOP8_1D27_5X4X1_7MM]  52.22 39.31 180 bottom
U3  SGM7222YWQ10/TR  [WQFN10_0D4_1_8X1_4X0_75MM]  60.28 29.79 90 top
U4  LAN9512I-JZX  [QFN64_0D5_9X9MM]  50.59 32.23 90 top
U5  USB2514Bi-AEZG-TR  [QFN36_0D5_6X6MM]  98.4 69.45 180 top
U6  UM805RE  [SOT_143]  79.57 74.16 270 bottom
U7  MIC2026-1YM-TR  [SOIC8_1D27_4_9X3_9MM]  107.4 71.85 270 top
U8  TPD4E05U06DQAR  [USON10_0D5_2D5X1X0D5MM]  108.82 49.36 180 bottom
U9  TPD4E05U06DQAR  [USON10_0D5_2D5X1X0D5MM]  105.39 48.83 180 bottom
U10  TPD4E05U06DQAR  [USON10_0D5_2D5X1X0D5MM]  102.06 47.84 180 top
U11  TPD4E05U06DQAR  [USON10_0D5_2D5X1X0D5MM]  49.05 22.56 180 top
U12  PCA9535RGER  [VQFN24_0D5_4X4X1MM]  29.43 70.61 90 top
U13  XC6206P332MR-G  [SOT23]  60.91 4.61 180 top
U14  SGM7222YWQ10/TR  [WQFN10_0D4_1_8X1_4X0_75MM]  37.46 24.45 270 bottom
U15  CH343P  [QFN16G_0D5_3X3X0_85MM]  36.89 54.44 0 top
U16  PCF8563T/5,518  [SOIC8_1D27_4_9X3_9MM]  13.21 70.4 270 top
U17  AT24C256C-SSHL-T  [SOIC8_1D27_4_9X3_9MM]  64.82 79.48 270 bottom
U18  74LVC1G07GW  [SOT353]  16.13 73.39 90 bottom
U19  ATECC608A-MAHDA-S  [UDFN8_0D5_2X3X0_6MM]  36.12 70.88 90 top
U20  SN74LVC2G241DCUR  [U_8_DCU]  37.43 60.98 0 top
U21  XC6206P182MR  [SOT23]  73.61 74.16 90 bottom
U22  B0505S-1WR3  [CONVERTER4P_2R54_11R6X6MM]  59.04 19.57 270 top
U23  SY6280AAC  [SOT23-5]  79.59 20.7 0 top
U24  SN74LVC2G241DCUR  [U_8_DCU]  74.33 20.6 90 bottom
U28  MQ7813T120  [MOUDLE8P_2D54_27_9X17_8MM]  19.9 32.71 180 top
U29  TPD4E05U06DQAR  [USON10_0D5_2D5X1X0D5MM]  16.53 39.8 0 bottom
U30  TPD4E05U06DQAR  [USON10_0D5_2D5X1X0D5MM]  22.49 39.95 0 bottom
U33  FM93C66A-SO-T-G  [SOP8_1D27_4_9X3_9MM]  32.84 34.75 270 bottom
U*  U*  []  66.5 57.25 270 bottom
X1  25MHz  [X4-SMD-3_2X2_5X1_0MM]  53.33 23.3 180 top
X2  24MHz 20pF  [X4-SMD-3_2X2_5X1_0MM]  101.83 62.54 90 top
X3  32.768KHz  12.5pF  [X2_SMD_3_2X1_5MM]  7.26 68.86 180 top

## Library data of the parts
B1 = ACTIVE BUZZER
C1-C3 C5-C13 C15-C18 C20-C24 C28-C31 C33 C34 C42 C44 C48 C56-C58 C69 C71 C73-C82 C84 C86-C89 C92 C95 C97 C99 C102-C110 C112-C118 C124 C129 C135 C136 C145-C159 C163 C166-C169 C502 = CC
C4 C14 C19 C32 C37 C38 C40 C41 C43 C45-C47 C49-C55 C59-C68 C83 C85 C90 C91 C93 C94 C96 C98 C100 C101 C111 C119 C120 C125 C131 C160 C204 C500 C501 C504 C508 C509 = CC: signal model: DEFAULT_CAPACITOR_100000pF_1_2
C35 C36 = CC: signal model: DEFAULT_CAPACITOR_1e+06pF_1_2
C70 C72 = CC: signal model: DEFAULT_CAPACITOR_10000pF_1_2
C121-C123 C128 = CC: signal model: DEFAULT_CAPACITOR_33.000000pF_1_2
C126 C127 C144 = CT
C130 C132-C134 C503 = CC: signal model: DEFAULT_CAPACITOR_4.7e+06pF_1_2
D1-D3 D9-D11 D13 D24-D27 D29 D63 = D
D5 D12 D14-D23 D28 D30-D33 D37-D44 D50 D53-D60 D64 = DIODE TVS BI-DIR
D8 D34 = DIODE TVS
D51 D52 = BRIDGE RECTIFIERS DF
F1 F2 = Fuse
FB1-FB6 FB9 FB15 FB26 FB27 = FB
G1 = gdt_2p
J1 J12 = Header 1x2
J2 J13 = Header 2x7 13P
J3 = SOLDERING TERMINAL 4P
J4 = CM4_CON_A
J5 = CM4_CON_B
J6 = Toggle Switch_2CH
J8 = Dual USB A
J9 = HDMI_Type A_19P_320010999
J10 = RJ45_HanRun_HY911105T
J11 = USB2.0_Type C_16+4P-Vert
J14 J15 = MINI_PCIE_52P
J16 = Nano SIM Hloder_ST-SIM-N032
J17 J20 = Header 2X4
J18 = RJ45_LPJE101AGNL
J21 = Terminal 2X9
J22 J23 = Header 2X5
J24 = FPC 22+4P
J25 = JST_10+2P
J26 = MicroSD Card_9+4P
J62 = PCIe_M.2_Key M_75Pin
L2 L3 L15 = L
L4 L5 L19-L22 = CL
L11 = L: signal model: Graser_L11
L16 = CLT
MH1-MH4 MH6 MH7 MH10-MH14 = MHole
OSC1 = OSC_4P
Q1 = PMOS_9P
Q2 = PNP
Q3 = NMOS_123
R1-R21 R24 R25 R27 R28 R30-R40 R42 R44-R47 R50-R56 R59 R64 R69 R71-R73 R78-R90 R92-R111 R113-R120 R122-R131 R151-R161 R163-R166 R175-R178 R181 R530-R532 R573 R632 R633 R651-R654 = R
R26 R29 R48 R49 R57 R70 R91 R112 = R: signal model: DEFAULT_RESISTOR_0.001OHM_1_2
R41 R43 R60-R63 R65-R68 R74 R75 = R: signal model: DEFAULT_RESISTOR_10000OHM_1_2
R58 = R: signal model: DEFAULT_RESISTOR_12000OHM_1_2
R182 R183 = VDR
SW1 = BUTTON 2+2P
T1 = LP82441ANL
TP1-TP34 = Test Point
U1 U2 = SGM61630A
U3 U14 = SGM7222
U4 = LAN9512/4
U5 = USB251xB/xBi
U6 = UM805_4P
U7 = MIC2026
U8 U9 = TPD4E05U06DQAR: signal model: TPD4E05U06DQAR_USON10_0D5_2D5X1X0D5MM_TPD4E05U06DQAR_TPD4E05U06DQAR
U10 U11 U29 U30 = TPD4E05U06DQAR
U12 = PCA9535RGE
U13 U21 = LDO_3P
U15 = CH343P
U16 = DS1337
U17 = CAT24C256
U18 = SN74LVC1G07DCK
U19 = ATECC608A
U20 U24 = SN74LVC2G241
U22 = Isolate DCDC
U23 = SY6280
U28 = Module_MQ7813
U33 = FM93C66A
X1 X2 = XTAL_4P
X3 = XTAL_2P

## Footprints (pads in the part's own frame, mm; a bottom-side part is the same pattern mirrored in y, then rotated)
AVX_B
  rrect 1.143x2.286 smd: 1(-1.46,0) 2(1.46,0)
BUTTON4P_7_2X7_5X7MM
  round 2 hole 1.1: 1(-2.25,2.45) 2(2.25,2.45)
  round 2 hole 1.2: 3(3.6,0) 4(-3.6,0)
BUZZER2P_8D4_9_6X9_6X5_5MM
  rrect 1.6x3.2 smd: 1(0,4.6) 2(0,-4.6)
C0201
  rrect 0.279x0.318 smd: 1(-0.255,0) 2(0.255,0)
C0402
  rrect 0.5x0.5 smd: 1(-0.463,0) 2(0.463,0)
C0603
  rrect 0.889x0.889 smd: 1(-0.762,0) 2(0.762,0)
C0805
  rrect 1.016x1.397 smd: 1(-0.889,0) 2(0.889,0)
C1206
  rect 1.397x1.626 smd: 1(-1.41,0) 2(1.41,0)
CAP_5D0_9X3X12MM
  round 1.6 hole 0.9: 1(-2.35,-0.8) 2(2.35,0.8)
CON_MINIPEX_067_SMT_RA_M2_KEY_M
  round 1.2 hole 1.2 unplated: (-10,0)
  round 1.7 hole 1.7 unplated: (10,0)
  rrect 0.3x1.8 smd: 1(-9.25,4.9) 2(-9,-1.9) 3(-8.75,4.9) 4(-8.5,-1.9) 5(-8.25,4.9) 6(-8,-1.9) 7(-7.75,4.9) 8(-7.5,-1.9) 9(-7.25,4.9) 10(-7,-1.9) 11(-6.75,4.9) 12(-6.5,-1.9) 13(-6.25,4.9) 14(-6,-1.9) 15(-5.75,4.9) 16(-5.5,-1.9) 17(-5.25,4.9) 18(-5,-1.9) 19(-4.75,4.9) 20(-4.5,-1.9) 21(-4.25,4.9) 22(-4,-1.9) 23(-3.75,4.9) 24(-3.5,-1.9) 25(-3.25,4.9) 26(-3,-1.9) 27(-2.75,4.9) 28(-2.5,-1.9) 29(-2.25,4.9) 30(-2,-1.9) 31(-1.75,4.9) 32(-1.5,-1.9) 33(-1.25,4.9) 34(-1,-1.9) 35(-0.75,4.9) 36(-0.5,-1.9) 37(-0.25,4.9) 38(0,-1.9) 39(0.25,4.9) 40(0.5,-1.9) 41(0.75,4.9) 42(1,-1.9) 43(1.25,4.9) 44(1.5,-1.9) 45(1.75,4.9) 46(2,-1.9) 47(2.25,4.9) 48(2.5,-1.9) 49(2.75,4.9) 50(3,-1.9) 51(3.25,4.9) 52(3.5,-1.9) 53(3.75,4.9) 54(4,-1.9) 55(4.25,4.9) 56(4.5,-1.9) 57(4.75,4.9) 58(5,-1.9) 67(7.25,4.9) 68(7.5,-1.9) 69(7.75,4.9) 70(8,-1.9) 71(8.25,4.9) 72(8.5,-1.9) 73(8.75,4.9) 74(9,-1.9) 75(9.25,4.9)
  rect 1.2x2.7 smd: 76(-10.35,4.5) 77(10.35,4.5)
CONVERTER4P_2R54_11R6X6MM
  oval 1.3x0.8 hole 0.75x0.55: 1(-3.81,0) 2(-1.27,0) 3(1.27,0) 4(3.81,0)
D0402
  rrect 0.5x0.5 smd: 1(-0.463,0) 2(0.463,0)
DF40_100P_0D4_22_6X3_38X1_5MM
  rrect 0.7x0.2 smd: 1(1.54,-9.8) 2(-1.54,-9.8) 3(1.54,-9.4) 4(-1.54,-9.4) 5(1.54,-9) 6(-1.54,-9) 7(1.54,-8.6) 8(-1.54,-8.6) 9(1.54,-8.2) 10(-1.54,-8.2) 11(1.54,-7.8) 12(-1.54,-7.8) 13(1.54,-7.4) 14(-1.54,-7.4) 15(1.54,-7) 16(-1.54,-7) 17(1.54,-6.6) 18(-1.54,-6.6) 19(1.54,-6.2) 20(-1.54,-6.2) 21(1.54,-5.8) 22(-1.54,-5.8) 23(1.54,-5.4) 24(-1.54,-5.4) 25(1.54,-5) 26(-1.54,-5) 27(1.54,-4.6) 28(-1.54,-4.6) 29(1.54,-4.2) 30(-1.54,-4.2) 31(1.54,-3.8) 32(-1.54,-3.8) 33(1.54,-3.4) 34(-1.54,-3.4) 35(1.54,-3) 36(-1.54,-3) 37(1.54,-2.6) 38(-1.54,-2.6) 39(1.54,-2.2) 40(-1.54,-2.2) 41(1.54,-1.8) 42(-1.54,-1.8) 43(1.54,-1.4) 44(-1.54,-1.4) 45(1.54,-1) 46(-1.54,-1) 47(1.54,-0.6) 48(-1.54,-0.6) 49(1.54,-0.2) 50(-1.54,-0.2) 51(1.54,0.2) 52(-1.54,0.2) 53(1.54,0.6) 54(-1.54,0.6) 55(1.54,1) 56(-1.54,1) 57(1.54,1.4) 58(-1.54,1.4) 59(1.54,1.8) 60(-1.54,1.8) 61(1.54,2.2) 62(-1.54,2.2) 63(1.54,2.6) 64(-1.54,2.6) 65(1.54,3) 66(-1.54,3) 67(1.54,3.4) 68(-1.54,3.4) 69(1.54,3.8) 70(-1.54,3.8) 71(1.54,4.2) 72(-1.54,4.2) 73(1.54,4.6) 74(-1.54,4.6) 75(1.54,5) 76(-1.54,5) 77(1.54,5.4) 78(-1.54,5.4) 79(1.54,5.8) 80(-1.54,5.8) 81(1.54,6.2) 82(-1.54,6.2) 83(1.54,6.6) 84(-1.54,6.6) 85(1.54,7) 86(-1.54,7) 87(1.54,7.4) 88(-1.54,7.4) 89(1.54,7.8) 90(-1.54,7.8) 91(1.54,8.2) 92(-1.54,8.2) 93(1.54,8.6) 94(-1.54,8.6) 95(1.54,9) 96(-1.54,9) 97(1.54,9.4) 98(-1.54,9.4) 99(1.54,9.8) 100(-1.54,9.8)
DF40_100P_0D4_22_6X3_38X1_5MM_101_200
  rrect 0.7x0.2 smd: 101(1.54,-9.8) 102(-1.54,-9.8) 103(1.54,-9.4) 104(-1.54,-9.4) 105(1.54,-9) 106(-1.54,-9) 107(1.54,-8.6) 108(-1.54,-8.6) 109(1.54,-8.2) 110(-1.54,-8.2) 111(1.54,-7.8) 112(-1.54,-7.8) 113(1.54,-7.4) 114(-1.54,-7.4) 115(1.54,-7) 116(-1.54,-7) 117(1.54,-6.6) 118(-1.54,-6.6) 119(1.54,-6.2) 120(-1.54,-6.2) 121(1.54,-5.8) 122(-1.54,-5.8) 123(1.54,-5.4) 124(-1.54,-5.4) 125(1.54,-5) 126(-1.54,-5) 127(1.54,-4.6) 128(-1.54,-4.6) 129(1.54,-4.2) 130(-1.54,-4.2) 131(1.54,-3.8) 132(-1.54,-3.8) 133(1.54,-3.4) 134(-1.54,-3.4) 135(1.54,-3) 136(-1.54,-3) 137(1.54,-2.6) 138(-1.54,-2.6) 139(1.54,-2.2) 140(-1.54,-2.2) 141(1.54,-1.8) 142(-1.54,-1.8) 143(1.54,-1.4) 144(-1.54,-1.4) 145(1.54,-1) 146(-1.54,-1) 147(1.54,-0.6) 148(-1.54,-0.6) 149(1.54,-0.2) 150(-1.54,-0.2) 151(1.54,0.2) 152(-1.54,0.2) 153(1.54,0.6) 154(-1.54,0.6) 155(1.54,1) 156(-1.54,1) 157(1.54,1.4) 158(-1.54,1.4) 159(1.54,1.8) 160(-1.54,1.8) 161(1.54,2.2) 162(-1.54,2.2) 163(1.54,2.6) 164(-1.54,2.6) 165(1.54,3) 166(-1.54,3) 167(1.54,3.4) 168(-1.54,3.4) 169(1.54,3.8) 170(-1.54,3.8) 171(1.54,4.2) 172(-1.54,4.2) 173(1.54,4.6) 174(-1.54,4.6) 175(1.54,5) 176(-1.54,5) 177(1.54,5.4) 178(-1.54,5.4) 179(1.54,5.8) 180(-1.54,5.8) 181(1.54,6.2) 182(-1.54,6.2) 183(1.54,6.6) 184(-1.54,6.6) 185(1.54,7) 186(-1.54,7) 187(1.54,7.4) 188(-1.54,7.4) 189(1.54,7.8) 190(-1.54,7.8) 191(1.54,8.2) 192(-1.54,8.2) 193(1.54,8.6) 194(-1.54,8.6) 195(1.54,9) 196(-1.54,9) 197(1.54,9.4) 198(-1.54,9.4) 199(1.54,9.8) 200(-1.54,9.8)
DO_214AA_SMB
  rrect 2.032x2.286 smd: 1(-2.032,0) 2(2.032,0)
DO_214AB_SMC
  rrect 2.286x4.064 smd: 1(-3.683,0) 2(3.683,0)
ELECTRO_SMD_6_6X6_6MM
  rrect 1x3 smd: 1(0,-2.45) 2(0,2.45)
F0603
  rrect 1x1 smd: 1(-0.8,0) 2(0.8,0)
FPC22_0D5_16_7X3_5X3_95MM_90D
  rrect 0.5x1.5 smd: 1(5.25,1.1) 2(4.75,-1.1) 3(4.25,1.1) 4(3.75,-1.1) 5(3.25,1.1) 6(2.75,-1.1) 7(2.25,1.1) 8(1.75,-1.1) 9(1.25,1.1) 10(0.75,-1.1) 11(0.25,1.1) 12(-0.25,-1.1) 13(-0.75,1.1) 14(-1.25,-1.1) 15(-1.75,1.1) 16(-2.25,-1.1) 17(-2.75,1.1) 18(-3.25,-1.1) 19(-3.75,1.1) 20(-4.25,-1.1) 21(-4.75,1.1) 22(-5.25,-1.1)
  rrect 0.6x1.5 smd: SH1(-6.3,1.1) SH2(-6.3,-1.1) SH3(6.3,-1.1) SH4(6.3,1.1)
FUSE2P_HOLDER_9_73X5_03X3_81MM
  rrect 4.24x3.81 smd: 1(-3.185,0) 2(3.185,0)
GDT2P_4D0_4_5X3_2X2_7MM
  rrect 1x3.4 smd: 1(-2.25,0) 2(2.25,0)
HDMI19P_1D155_23_1X7_7X16_4MM
  round 1.7 hole 1.7 unplated: (-2,13.25) (1.5,0)
  round 0.8 hole 0.55: 1(0.5,1.9) 2(-0.5,2.478) 3(0.5,3.055) 4(-0.5,3.633) 5(0.5,4.21) 6(-0.5,4.788) 7(0.5,5.365) 8(-0.5,5.943) 9(0.5,6.52) 10(-0.5,7.098) 11(0.5,7.675) 12(-0.5,8.253) 13(0.5,8.83) 14(-0.5,9.408) 15(0.5,9.985) 16(-0.5,10.563) 17(0.5,11.14) 18(-0.5,11.718) 19(0.5,12.295)
  oval 1.7x3.4 hole 0.9x2.7: 20(-3.25,1.15) 21(-3.25,10.15) 22(3.25,3.75) 23(3.25,13.25)
HEADER2P_1D25_DIP
  round 0.9 hole 0.55: 1(0.625,0) 2(-0.625,0)
HEADER2X4P_2D54_SMD
  rrect 3.17x1.02 smd: 1(-2.715,3.81) 2(2.715,3.81) 3(-2.715,1.27) 4(2.715,1.27) 5(-2.715,-1.27) 6(2.715,-1.27) 7(-2.715,-3.81) 8(2.715,-3.81)
HEADER2X4P_2D54_SMD#2
  rrect 3.17x1.02 smd: 1(-2.115,3.81) 2(2.115,3.81) 3(-2.115,1.27) 4(2.115,1.27) 5(-2.115,-1.27) 6(2.115,-1.27) 7(-2.115,-3.81) 8(2.115,-3.81)
HEADER2X5P_2D54_SMD_FEMALE
  rrect 1.02x1.9 smd: 1(-5.08,2.85) 2(-5.08,-2.85) 3(-2.54,2.85) 4(-2.54,-2.85) 5(0,2.85) 6(0,-2.85) 7(2.54,2.85) 8(2.54,-2.85) 9(5.08,2.85) 10(5.08,-2.85)
HEADER2X7P_1D27_SMD_NP_EPT14
  round 1.05 hole 1.05 unplated: (-3.125,0) (3.125,0)
  rrect 0.74x2.4 smd: 1(-3.81,-1.95) 2(-3.81,1.95) 3(-2.54,-1.95) 4(-2.54,1.95) 5(-1.27,-1.95) 6(-1.27,1.95) 7(0,-1.95) 8(0,1.95) 9(1.27,-1.95) 10(1.27,1.95) 11(2.54,-1.95) 12(2.54,1.95) 13(3.81,-1.95)
JST10_2P_1D0_12_35X3_2X4_5MM
  rrect 0.5x1.2 smd: 1(-4.5,0) 2(-3.5,0) 3(-2.5,0) 4(-1.5,0) 5(-0.5,0) 6(0.5,0) 7(1.5,0) 8(2.5,0) 9(3.5,0) 10(4.5,0)
  rrect 0.8x1.5 smd: S1(-5.7,-2.95) S2(5.7,-2.95)
L4P_0_85X0_65MM
  rrect 0.3x0.3 smd: 1(-0.25,-0.3) 2(-0.25,0.3) 3(0.25,0.3) 4(0.25,-0.3)
L4P_10X8_7X6_5MM
  rrect 2.7x2.7 smd: 1(3.1,-3.8) 2(-3.1,-3.8) 3(-3.1,3.8) 4(3.1,3.8)
L4X4MM
  rect 1.6x3 smd: 1(-1.5,0) 2(1.5,0)
L6_6X7X1_6MM
  rrect 1.9x3.3 smd: 1(-2.85,0) 2(2.85,0)
L0402
  rrect 0.5x0.5 smd: 1(-0.463,0) 2(0.463,0)
L0603
  rrect 0.889x0.889 smd: 1(-0.762,0) 2(0.762,0)
L4242
  rrect 1.55x3.1 smd: 1(-1.75,0) 2(1.75,0)
MICRO_SD_ST_TF_003A_16_1X14_5MM
  round 0.9 hole 0.9 unplated: (10.5,3.05) (10.5,-4.95)
  rrect 1.6x0.7 smd: 1(0,2.25) 2(0,1.15) 3(0,0.05) 4(0,-1.05) 5(0,-2.15) 6(0,-3.25) 7(0,-4.35) 8(0,-5.45) 9(0,-6.55)
  rrect 1.6x1.4 smd: 10(0.6,-7.85)
  rrect 2.2x1.4 smd: 11(10.1,-7.85) 12(10.1,7.85)
  rrect 1.4x1.8 smd: 13(0.5,6.95)
MOUDLE8P_2D54_27_9X17_8MM
  round 1.9 hole 1.2: 1(-11.43,-7.62) 2(-8.89,-7.62) 3(8.89,-7.62) 4(11.43,-7.62) 5(11.43,7.62) 6(8.89,7.62) 7(-8.89,7.62) 8(-11.43,7.62)
PCIE52_0D8_56X30_2X4MM
  round 1.1 hole 1.1 unplated: (0,-12.5)
  round 1.6 hole 1.6 unplated: (0,12.5)
  rect 2x0.55 smd: 1(-4.1,11.8) 2(4.1,11.4) 3(-4.1,11) 4(4.1,10.6) 5(-4.1,10.2) 6(4.1,9.8) 7(-4.1,9.4) 8(4.1,9) 9(-4.1,8.6) 10(4.1,8.2) 11(-4.1,7.8) 12(4.1,7.4) 13(-4.1,7) 14(4.1,6.6) 15(-4.1,6.2) 16(4.1,5.8) 17(-4.1,2.2) 18(4.1,1.8) 19(-4.1,1.4) 20(4.1,1) 21(-4.1,0.6) 22(4.1,0.2) 23(-4.1,-0.2) 24(4.1,-0.6) 25(-4.1,-1) 26(4.1,-1.4) 27(-4.1,-1.8) 28(4.1,-2.2) 29(-4.1,-2.6) 30(4.1,-3) 31(-4.1,-3.4) 32(4.1,-3.8) 33(-4.1,-4.2) 34(4.1,-4.6) 35(-4.1,-5) 36(4.1,-5.4) 37(-4.1,-5.8) 38(4.1,-6.2) 39(-4.1,-6.6) 40(4.1,-7) 41(-4.1,-7.4) 42(4.1,-7.8) 43(-4.1,-8.2) 44(4.1,-8.6) 45(-4.1,-9) 46(4.1,-9.4) 47(-4.1,-9.8) 48(4.1,-10.2) 49(-4.1,-10.6) 50(4.1,-11) 51(-4.1,-11.4) 52(4.1,-11.8)
  rect 3.2x2.3 smd: 53(-3.5,-14.65) 54(-3.5,14.65)
PTH_3_1MM_8
  round 8.128 hole 3.1: 1(0,0)
PTH_3_73MM_5D8_PASTE
  round 4.3 hole 3.73: 1(0,0)
PTH_4_2MM_5D8
  round 5.8 hole 4.2: 1(0,0)
PTH_4_3MM_6D0
  round 6 hole 4.3: 1(0,0)
QFN16G_0D5_3X3X0_85MM
  rrect 0.6x0.25 smd: 1(-1.475,0.75) 2(-1.475,0.25) 3(-1.475,-0.25) 4(-1.475,-0.75) 9(1.475,-0.75) 10(1.475,-0.25) 11(1.475,0.25) 12(1.475,0.75)
  rrect 0.25x0.6 smd: 5(-0.75,-1.475) 6(-0.25,-1.475) 7(0.25,-1.475) 8(0.75,-1.475) 13(0.75,1.475) 14(0.25,1.475) 15(-0.25,1.475) 16(-0.75,1.475)
  rrect 1.6x1.6 smd: 17(0,0)
QFN36_0D5_6X6MM
  rrect 0.9x0.3 smd: 1(-2.85,2) 2(-2.85,1.5) 3(-2.85,1) 4(-2.85,0.5) 5(-2.85,0) 6(-2.85,-0.5) 7(-2.85,-1) 8(-2.85,-1.5) 9(-2.85,-2) 19(2.85,-2) 20(2.85,-1.5) 21(2.85,-1) 22(2.85,-0.5) 23(2.85,0) 24(2.85,0.5) 25(2.85,1) 26(2.85,1.5) 27(2.85,2)
  rrect 0.3x0.9 smd: 10(-2,-2.85) 11(-1.5,-2.85) 12(-1,-2.85) 13(-0.5,-2.85) 14(0,-2.85) 15(0.5,-2.85) 16(1,-2.85) 17(1.5,-2.85) 18(2,-2.85) 28(2,2.85) 29(1.5,2.85) 30(1,2.85) 31(0.5,2.85) 32(0,2.85) 33(-0.5,2.85) 34(-1,2.85) 35(-1.5,2.85) 36(-2,2.85)
  rrect 3.7x3.7 smd: 37(0,0)
QFN64_0D5_9X9MM
  rrect 0.25x0.7 smd: 1(-3.75,-4.45) 2(-3.25,-4.45) 3(-2.75,-4.45) 4(-2.25,-4.45) 5(-1.75,-4.45) 6(-1.25,-4.45) 7(-0.75,-4.45) 8(-0.25,-4.45) 9(0.25,-4.45) 10(0.75,-4.45) 11(1.25,-4.45) 12(1.75,-4.45) 13(2.25,-4.45) 14(2.75,-4.45) 15(3.25,-4.45) 16(3.75,-4.45) 33(3.75,4.45) 34(3.25,4.45) 35(2.75,4.45) 36(2.25,4.45) 37(1.75,4.45) 38(1.25,4.45) 39(0.75,4.45) 40(0.25,4.45) 41(-0.25,4.45) 42(-0.75,4.45) 43(-1.25,4.45) 44(-1.75,4.45) 45(-2.25,4.45) 46(-2.75,4.45) 47(-3.25,4.45) 48(-3.75,4.45)
  rrect 0.7x0.25 smd: 17(4.45,-3.75) 18(4.45,-3.25) 19(4.45,-2.75) 20(4.45,-2.25) 21(4.45,-1.75) 22(4.45,-1.25) 23(4.45,-0.75) 24(4.45,-0.25) 25(4.45,0.25) 26(4.45,0.75) 27(4.45,1.25) 28(4.45,1.75) 29(4.45,2.25) 30(4.45,2.75) 31(4.45,3.25) 32(4.45,3.75) 49(-4.45,3.75) 50(-4.45,3.25) 51(-4.45,2.75) 52(-4.45,2.25) 53(-4.45,1.75) 54(-4.45,1.25) 55(-4.45,0.75) 56(-4.45,0.25) 57(-4.45,-0.25) 58(-4.45,-0.75) 59(-4.45,-1.25) 60(-4.45,-1.75) 61(-4.45,-2.25) 62(-4.45,-2.75) 63(-4.45,-3.25) 64(-4.45,-3.75)
  rrect 5x5 smd: 65(0,0)
R0201
  rrect 0.279x0.318 smd: 1(-0.255,0) 2(0.255,0)
R0402
  rrect 0.5x0.5 smd: 1(-0.463,0) 2(0.463,0)
R0603
  rrect 0.889x0.889 smd: 1(-0.762,0) 2(0.762,0)
R0805
  rrect 1.016x1.397 smd: 1(-0.889,0) 2(0.889,0)
R1206
  rect 1.397x1.626 smd: 1(-1.41,0) 2(1.41,0)
RJ45-7499010211A
  round 1.016 hole 3.251 unplated: (-1.27,-6.35) (10.16,-6.35)
  rect 1.524x1.524 hole 1.016: 1(0,0)
  round 1.524 hole 1.016: 2(1.27,2.54) 3(2.54,0) 4(3.81,2.54) 5(5.08,0) 6(6.35,2.54) 7(7.62,0) 8(8.89,2.54) 9(-1.88,-11.252) 10(0.66,-9.728) 11(8.23,-11.252) 12(10.77,-9.728)
  round 2.286 hole 1.6: 13(-3.429,-3.302) 14(12.319,-3.302)
RJ45_12_2P_2D54_16_3X15_8X12_85MM
  round 3.25 hole 3.25 unplated: (-6.35,0) (6.35,0)
  round 1.3 hole 0.9: 1(-4.445,9.12) 2(-3.175,7.34) 3(-1.905,9.12) 4(-0.635,7.34) 5(0.635,9.12) 6(1.905,7.34) 7(3.175,9.12) 8(4.445,7.34)
  round 1.6 hole 1.2: 9(6.595,5.1) 10(4.305,5.1) 11(-4.305,5.1) 12(-6.595,5.1)
  round 1.9 hole 1.4: 13(8.05,3.56) 14(-8.05,3.56)
SIM6_4P_1D27_14X12X1_4MM
  rrect 0.9x1.2 smd: C1(-3.175,0) C2(-0.635,0) C3(1.905,0) C5(-1.905,0) C6(0.635,0) C7(3.175,0)
  rrect 1.3x1.8 smd: G1(-5.855,-4.1) G2(5.845,-4.1) G3(5.845,-12.9) SW(-5.855,-12.9)
SMD4P_4D7X3D8MM
  rrect 1.2x1.9 smd: 1(1.2,3) 2(-1.2,3) 3(-1.2,-3) 4(1.2,-3)
SOD_123
  rrect 1.397x1.397 smd: 1(-1.651,0) 2(1.651,0)
SOD_323
  rrect 1x0.8 smd: 1(-1.2,0) 2(1.2,0)
SOD_523
  rrect 0.762x0.7 smd: 1(-0.8,0) 2(0.8,0)
SOIC8_1D27_4_9X3_9MM
  rrect 0.6x1.55 smd: 1(-1.905,-2.7) 2(-0.635,-2.7) 3(0.635,-2.7) 4(1.905,-2.7) 5(1.905,2.7) 6(0.635,2.7) 7(-0.635,2.7) 8(-1.905,2.7)
SOLDERING_TERMINAL_4P_9X6_3X5MM
  round 2.5 hole 1.5: 1(-2.5,2.75) 2(-2.5,-2.75) 3(2.5,-2.75) 4(2.5,2.75)
SON8P_1D27_5X6X1MM
  rrect 0.8x0.65 smd: 1(-2.802,1.905) 2(-2.802,0.635) 3(-2.802,-0.635) 4(-2.802,-1.905) 5(2.802,-1.905) 6(2.802,-0.635) 7(2.802,0.635) 8(2.802,1.905)
  rrect 4.27x4.46 smd: 9(0.337,0)
SOP8_1D27_4_9X3_9MM
  rrect 0.6x1.55 smd: 1(-1.905,-2.7) 2(-0.635,-2.7) 3(0.635,-2.7) 4(1.905,-2.7) 5(1.905,2.7) 6(0.635,2.7) 7(-0.635,2.7) 8(-1.905,2.7)
SOP8_1D27_5X4X1_7MM
  rrect 1.375x0.6 smd: 1(-2.51,1.905) 2(-2.51,0.635) 3(-2.51,-0.635) 4(-2.51,-1.905) 5(2.51,-1.905) 6(2.51,-0.635) 7(2.51,0.635) 8(2.51,1.905)
  rrect 2.35x3.25 smd: 9(0,0)
SOT23
  rrect 1.016x1.143 smd: 1(-0.889,-1.016) 2(0.889,-1.016) 3(0,1.016)
SOT23-5
  rect 0.635x1.016 smd: 1(-0.953,-1.295) 2(0,-1.295) 3(0.953,-1.295) 4(0.953,1.295) 5(-0.953,1.295)
SOT353
  rrect 0.3x0.7 smd: 1(-0.65,-1) 2(0,-1) 3(0.65,-1) 4(0.65,1) 5(-0.65,1)
SOT_143
  rect 1.219x1.397 smd: 1(-0.75,-1.1)
  rect 1.016x1.397 smd: 2(0.95,-1.1) 3(0.95,1.1) 4(-0.95,1.1)
ST-USB-201C
  rect 1.321x1.321 hole 0.914: A1(3.5,-5.33)
  round 1.321 hole 0.914: A2(1,-5.33) A3(-1,-5.33) A4(-3.5,-5.33) B1(3.5,-2.71) B2(1,-2.71) B3(-1,-2.71) B4(-3.5,-2.71)
  round 3 hole 2.3: S1(6.57,-5.68) S2(-6.57,-5.68) S3(-6.57,0) S4(6.57,0)
SW6P_2D5_9X3_5X3_5MM
  round 1.4 hole 0.8: 1(-2.5,-1.6) 2(0,-1.6) 3(2.5,-1.6) 4(2.5,1.6) 5(0,1.6) 6(-2.5,1.6)
TERMINAL_2P_5D08
  rect 2.6x2.6 hole 1.45: 1(-2.54,0)
  round 2.6 hole 1.45: 2(2.54,0)
TERMINAL_2X9P_3D81_35_38X13_3X15_2MM
  rect 1.9x1.9 hole 1.4: 1(-15.24,0)
  round 1.9 hole 1.4: 2(-15.24,-3.5) 3(-11.43,0) 4(-11.43,-3.5) 5(-7.62,0) 6(-7.62,-3.5) 7(-3.81,0) 8(-3.81,-3.5) 9(0,0) 10(0,-3.5) 11(3.81,0) 12(3.81,-3.5) 13(7.62,0) 14(7.62,-3.5) 15(11.43,0) 16(11.43,-3.5) 17(15.24,0) 18(15.24,-3.5)
TP35S_SMD
  rrect 0.9x0.9 smd: 1(0,0)
TRF24P_1D0_15_1X7_1X4MM
  rrect 0.6x1.4 smd: 1(-5.5,-4.6) 2(-4.5,-4.6) 3(-3.5,-4.6) 4(-2.5,-4.6) 5(-1.5,-4.6) 6(-0.5,-4.6) 7(0.5,-4.6) 8(1.5,-4.6) 9(2.5,-4.6) 10(3.5,-4.6) 11(4.5,-4.6) 12(5.5,-4.6) 13(5.5,4.6) 14(4.5,4.6) 15(3.5,4.6) 16(2.5,4.6) 17(1.5,4.6) 18(0.5,4.6) 19(-0.5,4.6) 20(-1.5,4.6) 21(-2.5,4.6) 22(-3.5,4.6) 23(-4.5,4.6) 24(-5.5,4.6)
U_8_DCU
  rect 0.254x1.27 smd: 1(-0.749,-1.473) 2(-0.249,-1.473) 3(0.249,-1.473) 4(0.749,-1.473) 5(0.749,1.473) 6(0.249,1.473) 7(-0.249,1.473) 8(-0.749,1.473)
UDFN8_0D5_2X3X0_6MM
  rrect 0.25x0.7 smd: 1(-0.75,-1.45) 2(-0.25,-1.45) 3(0.25,-1.45) 4(0.75,-1.45) 5(0.75,1.45) 6(0.25,1.45) 7(-0.25,1.45) 8(-0.75,1.45)
  rrect 1.7x1.3 smd: 9(0,0)
USB2_0_TYPE_C_14X3D16X8D94MM
  round 0.55 hole 0.4: A1(2.925,-0.375) A4(2.025,-0.375) A5(1.125,-0.375) A6(0.225,-0.375) A7(-0.675,-0.375) A9(-2.025,-0.375) A12(-2.925,-0.375) B1(-2.925,0.375) B4(-2.025,0.375) B5(-1.125,0.375) B6(-0.225,0.375) B7(0.675,0.375) B9(2.025,0.375) B12(2.925,0.375)
  oval 2.3x0.8 hole 1.8x0.5: S1(-3.05,1.43) S4(-3.05,-1.43)
  oval 1.6x0.8 hole 1.1x0.5: S2(3.05,1.43) S3(3.05,-1.43)
USON10_0D5_2D5X1X0D5MM
  oval 0.2x0.7 smd: 1(-1,-0.45) 2(-0.5,-0.45) 4(0.5,-0.45) 5(1,-0.45) 6(1,0.45) 7(0.5,0.45) 9(-0.5,0.45) 10(-1,0.45)
  rrect 0.4x0.7 smd: 3(0,-0.45) 8(0,0.45)
VQFN24_0D5_4X4X1MM
  oval 0.7x0.24 smd: 1(-1.95,1.25) 2(-1.95,0.75) 3(-1.95,0.25) 4(-1.95,-0.25) 5(-1.95,-0.75) 6(-1.95,-1.25) 13(1.95,-1.25) 14(1.95,-0.75) 15(1.95,-0.25) 16(1.95,0.25) 17(1.95,0.75) 18(1.95,1.25)
  oval 0.24x0.7 smd: 7(-1.25,-1.95) 8(-0.75,-1.95) 9(-0.25,-1.95) 10(0.25,-1.95) 11(0.75,-1.95) 12(1.25,-1.95) 19(1.25,1.95) 20(0.75,1.95) 21(0.25,1.95) 22(-0.25,1.95) 23(-0.75,1.95) 24(-1.25,1.95)
  rrect 2.5x2.5 smd: 25(0,0)
WQFN10_0D4_1_8X1_4X0_75MM
  rect 0.22x0.75 smd: 1(-0.2,-0.575)
  rect 0.22x0.65 smd: 2(0.2,-0.625) 6(0.2,0.625) 7(-0.2,0.625)
  rect 0.65x0.22 smd: 3(0.825,-0.4) 4(0.825,0) 5(0.825,0.4) 8(-0.825,0.4) 9(-0.825,0) 10(-0.825,-0.4)
X2_SMD_3_2X1_5MM
  rrect 0.762x1.524 smd: 1(-1.524,0) 2(1.524,0)
X4-SMD-3_2X2_5X1_0MM
  rect 1.321x1.067 smd: 1(-1.15,-0.925) 2(1.15,-0.925) 3(1.15,0.925) 4(-1.15,0.925)

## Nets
3V3_RS485: C204.1 J22.9 R532.2
5V_ISO_INPUT: C132.1 L11.1 U23.1(OUT)
5V_ISO_OUT: C134.1 J23.6 R117.2 R118.1 R163.1 TP32.1(TP)
5V_TYPC: C92.1 C93.1 C94.1 C95.1 C96.1 C99.2 D21.2 J11.A4 J11.A9 J11.B4 J11.B9 R32.2 TP20.1(TP) U13.3 U15.3 U15.9
+1.8V_OUT: C34.2 J4.88 J4.90 R112.2
+3.3V_OUT: C32.1 C33.2 J4.84 J4.86 R26.2 R29.2 R181.1
GND: C2.2 C3.2 C4.2 C6.2 C7.2 C8.2 C9.2 C10.2 C11.2 C12.2 C13.2 C14.2 C15.2 C16.2 C19.2 C20.2 C21.2 C22.2 C23.2 C24.2 C28.2 C29.2 C31.2 C32.2 C33.1 C34.1 C35.1 C36.2 C37.2 C38.2 C40.2 C41.2 C42.2 C43.2 C44.2 C45.2 C46.2 C47.2 C48.2 C49.2 C50.2 C51.2 C52.2 C53.2 C54.2 C55.2 C56.2 C57.2 C58.2 C59.2 C60.2 C61.2 C62.2 C63.2 C64.2 C65.2 C66.2 C67.2 C68.2 C69.1 C70.1 C71.1 C72.1 C73.2 C74.2 C75.2 C76.1 C77.2 C78.1 C79.2 C80.2 C81.2 C82.2 C83.2 C84.2 C85.2 C86.2 C87.2 C88.2 C89.2 C90.2 C91.2 C92.2 C93.2 C94.2 C95.2 C96.2 C97.2 C98.2 C99.1 C100.1 C101.1 C102.1 C103.2 C104.2 C105.2 C106.2 C107.2 C108.2 C110.1 C111.2 C112.1 C113.1 C114.1 C115.1 C116.1 C117.2 C118.2 C119.2 C120.2 C121.2 C122.2 C123.2 C124.2 C125.2 C126.2 C127.2 C128.2 C129.1 C130.2 C131.2 C132.2 C133.2 C136.1 C144.2 C145.2 C146.2 C150.2 C151.2 C152.2 C153.2 C159.1 C160.2 C163.2 C166.2 C167.2 C168.2 C169.2 C204.2 C500.2 C501.2 C502.2 C503.2 C504.2 C508.2 C509.2 D5.1 D8.1 D10.1 D11.1 D12.1 D14.1 D15.1 D16.1 D17.1 D18.1 D19.1 D20.1 D21.1 D22.1 D23.1 D28.1 D30.1 D31.1 D32.1 D33.1 D37.1 D38.1 D39.1 D40.1 D41.1 D42.1 D43.1 D44.1 D53.1 D54.1 D55.1 D56.1 D57.1 D58.1 D59.1 D60.1 D64.1 J1.2 J2.7 J2.8 J2.9 J2.10 J4.1 J4.2 J4.7 J4.8 J4.13 J4.14 J4.22 J4.23 J4.32 J4.33 J4.42 J4.43 J4.52 J4.53 J4.59 J4.60 J4.65 J4.66 J4.71 J4.74 J4.98 J5.107 J5.108 J5.113 J5.114 J5.119 J5.120 J5.125 J5.126 J5.131 J5.132 J5.137 J5.138 J5.144 J5.150 J5.155 J5.156 J5.161 J5.162 J5.167 J5.168 J5.173 J5.174 J5.179 J5.180 J5.185 J5.186 J5.191 J5.192 J5.197 J5.198 J6.1 J6.4 J9.2 J9.5 J9.8 J9.11 J9.14(UTILITY) J9.17 J10.8 J11.A1 J11.A12 J11.B1 J11.B12 J12.1 J13.8 J14.4 J14.9 J14.15 J14.18 J14.21 J14.26 J14.27 J14.29 J14.34 J14.35 J14.37 J14.40 J14.43 J14.50 J14.53 J14.54 J15.9 J15.15 J15.18 J15.21 J15.26 J15.27 J15.29 J15.34 J15.35 J15.37 J15.40 J15.43 J15.50 J15.53 J15.54 J16.C5 J16.G1 J16.G2 J16.G3 J17.1 J22.1 J22.7 J24.1 J24.4 J24.7 J24.10 J24.13 J24.16 J24.19 J24.SH1 J24.SH2 J24.SH3 J24.SH4 J25.10 J26.6(VSS) J26.10 J26.11 J26.12 J26.13 J62.1 J62.3 J62.9 J62.15 J62.21 J62.27 J62.33 J62.39 J62.45 J62.51 J62.57 J62.71 J62.73 J62.75 J62.76 J62.77 MH1.1(NC) MH2.1(NC) MH3.1(NC) MH4.1(NC) MH6.1(NC) MH7.1(NC) MH10.1(NC) OSC1.2 Q3.2(S) R7.2 R10.1 R12.2 R14.2 R17.1 R19.2 R21.2 R35.2 R37.2 R40.2 R42.1 R45.1 R48.2 R53.1 R54.1 R55.1 R56.1 R57.2 R58.2 R72.2 R73.2 R74.1 R75.1 R92.2 R93.2 R94.2 R95.2 R96.2 R97.2 R108.2 R119.2 R120.2 R123.1 R130.1 R161.1 R166.1 R183.2 R573.2 R632.2 R633.2 R651.1 SW1.1 SW1.3 SW1.4 TP2.1(TP) TP3.1(TP) TP4.1(TP) TP5.1(TP) TP6.1(TP) TP7.1(TP) TP8.1(TP) TP9.1(TP) TP13.1(TP) TP17.1(TP) U1.7 U1.9 U2.7 U2.9 U3.4 U4.29 U4.30 U4.32 U4.34 U4.65 U5.37 U6.1 U7.6 U8.3 U8.8 U9.3 U9.8 U10.3 U10.8 U11.3 U11.8 U12.9 U12.25 U13.1(VSS) U14.4 U15.2 U15.17 U16.4 U17.1 U17.2 U17.3 U17.4 U18.3 U19.4 U19.9 U20.1 U20.4 U21.1(VSS) U22.1 U23.2 U24.1 U24.4 U28.3(VOUT-) U29.3 U29.8 U30.3 U30.8 U33.5 X1.2 X1.4 X2.2 X2.4
GND_DO: J20.8 J21.12 R165.2 R166.2
GND_EARTH: C135.2 C158.2 C159.2 G1.1 J3.1 J3.2 J3.3 J3.4 J8.S1 J8.S2 J8.S3 J8.S4 J10.13 J10.14 J11.S1 J11.S2 J11.S3 J11.S4 J18.13 J18.14 J25.S1 J25.S2 MH11.1(NC) MH12.1(NC) MH13.1(NC) MH14.1(NC) R131.2 R161.2 R632.1 R633.1
GND_ISO: C134.2 D34.1 J21.5 J21.6 J21.17 J21.18 J23.5 R123.2 R165.1 U22.3(VOUT-)
GND_ISO_DI: J20.1 J20.2 J21.11
V3: C101.2 R91.2 U15.6
VCC_USB1: C76.2 C78.2 C82.1 C83.1 D16.2 FB5.1 U7.8
VCC_USB2: C77.1 C79.1 C84.1 C85.1 D17.2 FB6.2 U7.5(OUTB)
VDD18CORE: C6.1 C14.1 C19.1 U4.15 U4.38
VDD18ETHPLL: C502.1 FB3.1 U4.48
